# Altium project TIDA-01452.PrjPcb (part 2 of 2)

## Sheet TIDA-01452_Hart.SchDoc: Hart
size 431 x 279 mm; Date: Not shown in title block; ApprovedBy: Not shown in title block; CheckedBy: Not shown in title block; Author: Not shown in title block; CompanyName: Not shown in title block; DrawnBy: Il Han Kim; Engineer: Not shown in title block; Organization: Not shown in title block; Address1: Not shown in title block; Address2: Not shown in title block; Address3: Not shown in title block; Address4: Not shown in title block; DocumentNumber: 6; Revision: Use project parameter SCH_Rev; SheetNumber: 8; SheetTotal: 12; PageSetup: Record=PageOptions¦CenterHorizontal=True¦CenterVertical=True¦PrintScale=0.64¦XCorrection=1.00¦YCorrection=1.00¦PrintKind=0¦BorderSize=5000000¦LeftOffset=0¦BottomOffset=0¦Orientation=2¦PaperLength=1000¦PaperWidth=1000¦Scale=100¦PaperSource=15¦PrintQuality=600¦MediaType=1¦DitherType=10¦PrintScaleMode=1¦PaperKind=Letter
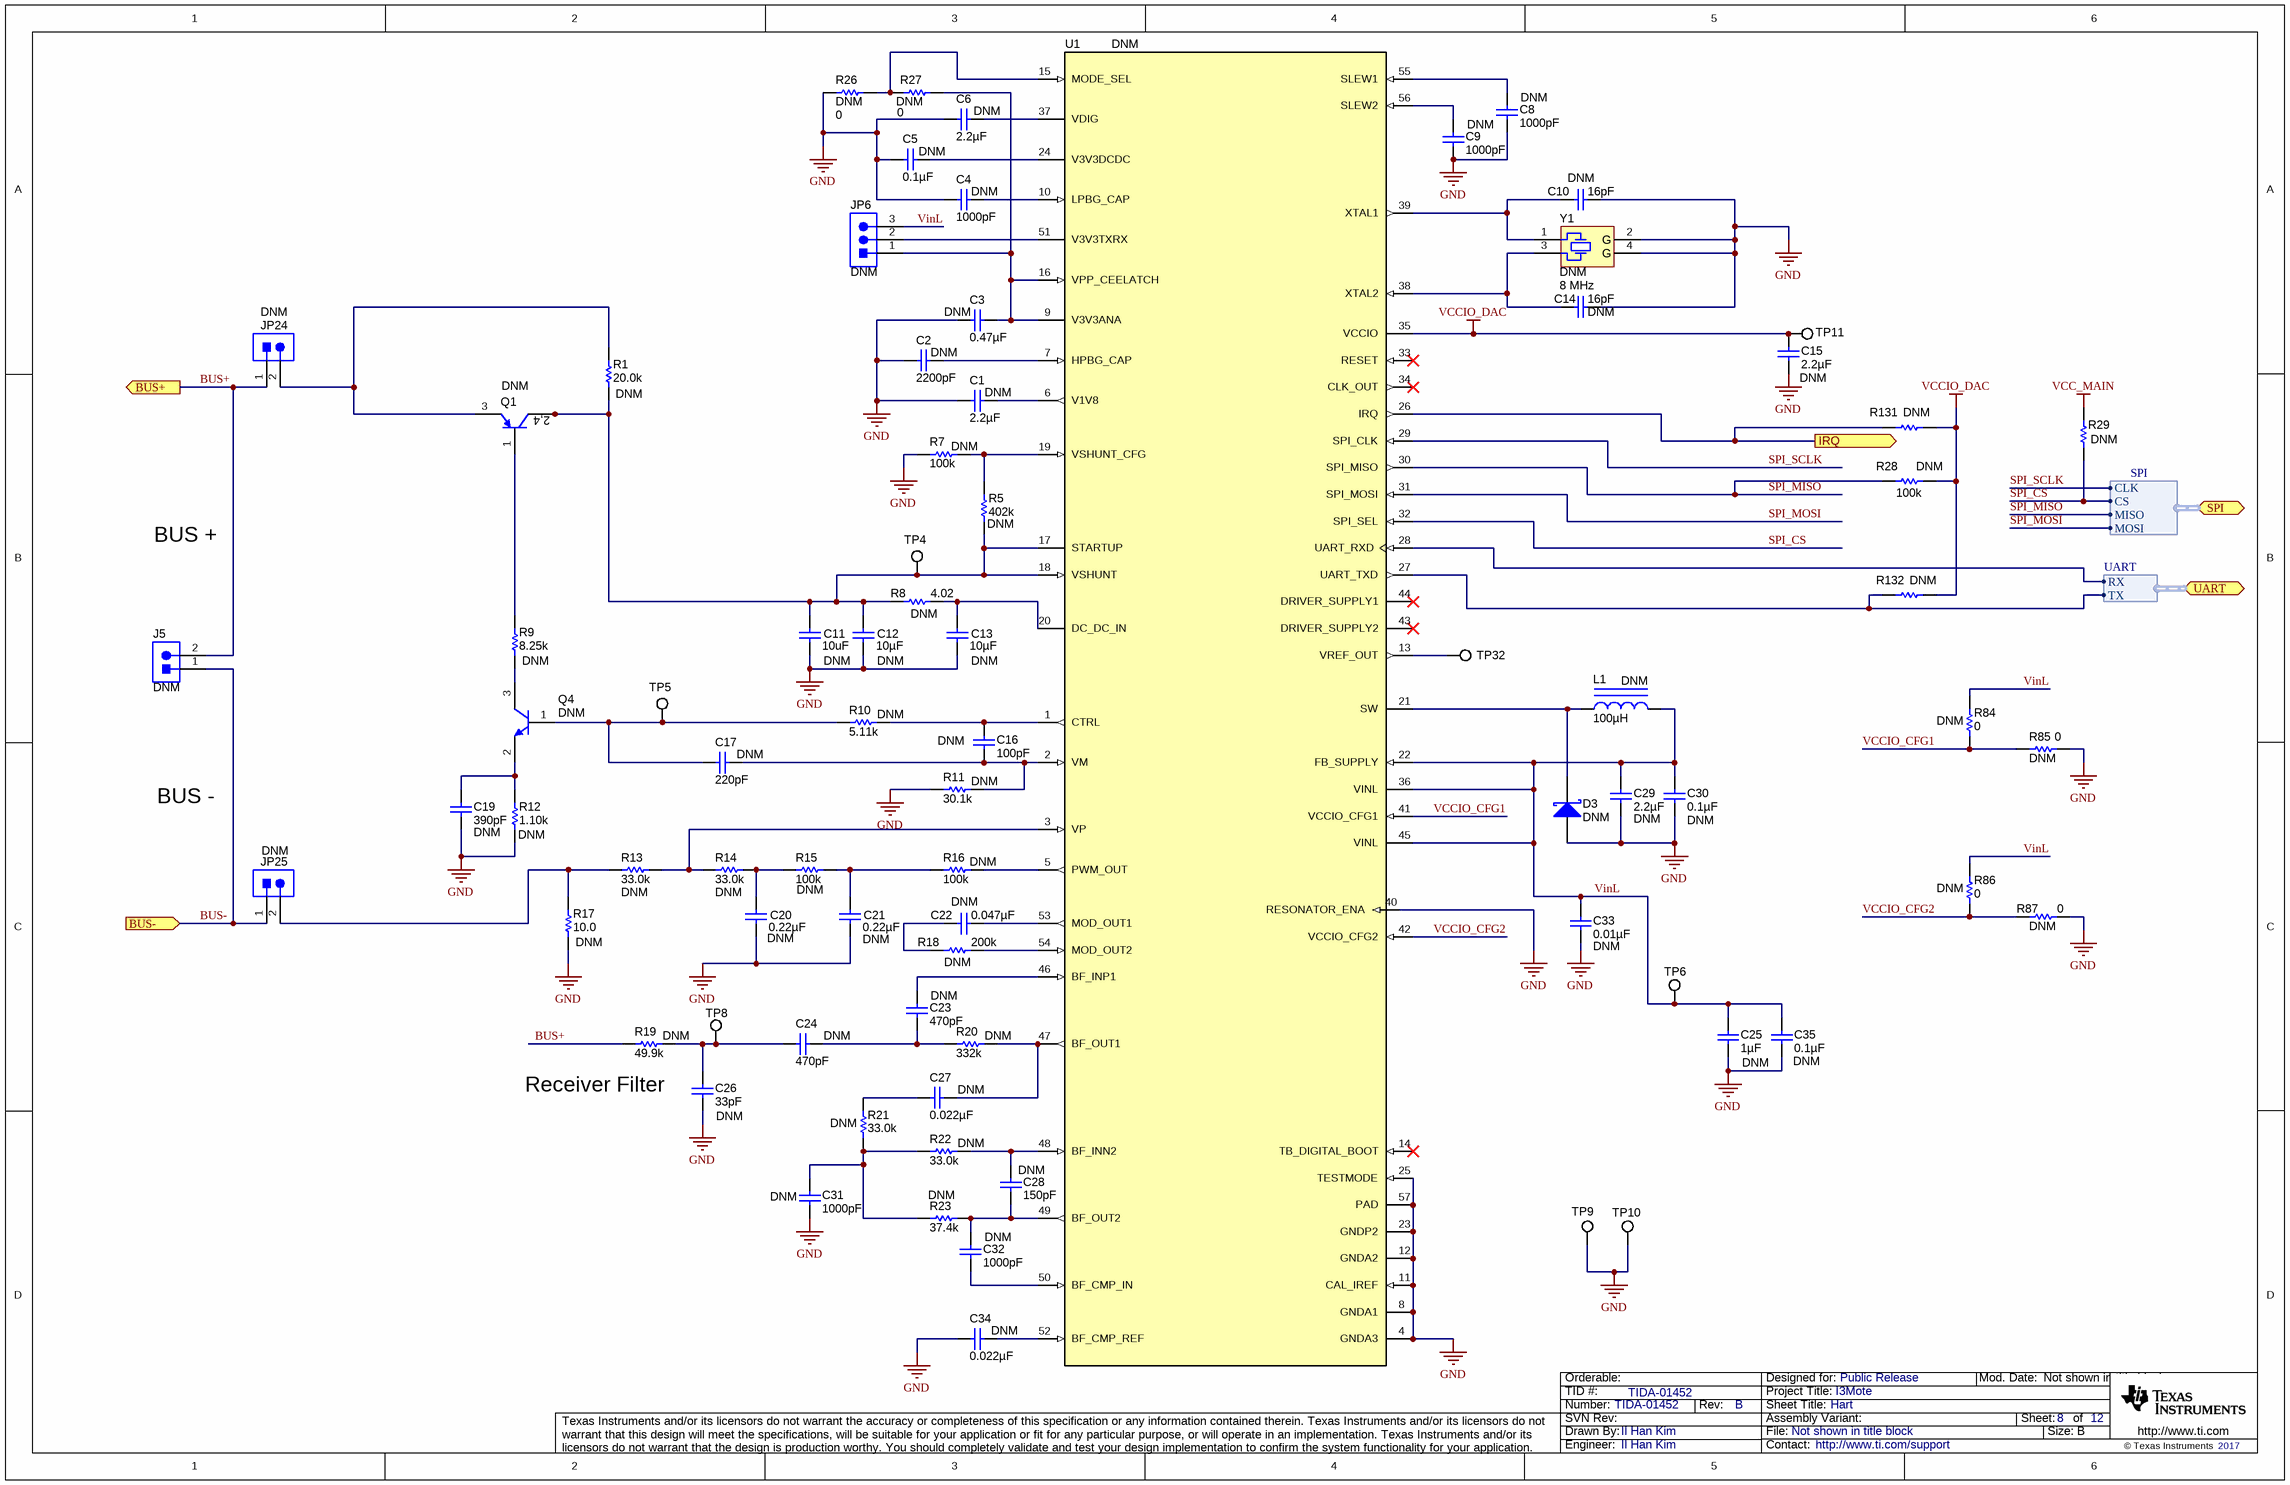
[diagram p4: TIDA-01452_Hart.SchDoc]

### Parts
C1  DNM  ValueDisplayed: 2.2µF  [0402]
C2  DNM  ValueDisplayed: 2200pF  [0402]
C3  DNM  ValueDisplayed: 0.47µF  [0402]
C4  DNM  ValueDisplayed: 1000pF  [0402]
C5  DNM  ValueDisplayed: 0.1µF  [0402]
C6  DNM  ValueDisplayed: 2.2µF  [0402]
C8  DNM  ValueDisplayed: 1000pF  [0402]
C9  DNM  ValueDisplayed: 1000pF  [0402]
C10  DNM  ValueDisplayed: 16pF  [0402]
C11  DNM  ValueDisplayed: 10uF  [1206_190]
C12  DNM  ValueDisplayed: 10µF  [1206_190]
C13  DNM  ValueDisplayed: 10µF  [1206_190]
C14  DNM  ValueDisplayed: 16pF  [0402]
C15  DNM  ValueDisplayed: 2.2µF  [0805_HV]
C16  DNM  ValueDisplayed: 100pF  [0402]
C17  DNM  ValueDisplayed: 220pF  [0402]
C19  DNM  ValueDisplayed: 390pF  [0402]
C20  DNM  ValueDisplayed: 0.22µF  [0603]
C21  DNM  ValueDisplayed: 0.22µF  [0603]
C22  DNM  ValueDisplayed: 0.047µF  [0402]
C23  DNM  ValueDisplayed: 470pF  [0402]
C24  DNM  ValueDisplayed: 470pF  [0402]
C25  DNM  ValueDisplayed: 1µF  [0402]
C26  DNM  ValueDisplayed: 33pF  [0402]
C27  DNM  ValueDisplayed: 0.022µF  [0402]
C28  DNM  ValueDisplayed: 150pF  [0402]
C29  DNM  ValueDisplayed: 2.2µF  [0805_HV]
C30  DNM  ValueDisplayed: 0.1µF  [0402]
C31  DNM  ValueDisplayed: 1000pF  [0402]
C32  DNM  ValueDisplayed: 1000pF  [0402]
C33  DNM  ValueDisplayed: 0.01µF  [0402]
C34  DNM  ValueDisplayed: 0.022µF  [0402]
C35  DNM  ValueDisplayed: 0.1µF  [0402]
D3  DNM  [sod-323]
J5  DNM  [TERM_BLK_ED555-2DS]
JP6  DNM  [CONN_TMM-103-01-T-S]
JP24  DNM  [CONN_TMM-102-01-T-S]
JP25  DNM  [CONN_TMM-102-01-T-S]
L1  DNM  ValueDisplayed: 100µH  [CBC3225]
Q1  DNM  [SOT-89-3]
Q4  DNM  [SOT-23]
R1  DNM  ValueDisplayed: 20.0k  [0603]
R5  DNM  ValueDisplayed: 402k  [0402]
R7  DNM  ValueDisplayed: 100k  [0402]
R8  DNM  ValueDisplayed: 4.02  [0603]
R9  DNM  ValueDisplayed: 8.25k  [0603]
R10  DNM  ValueDisplayed: 5.11k  [0402]
R11  DNM  ValueDisplayed: 30.1k  [0402]
R12  DNM  ValueDisplayed: 1.10k  [0603]
R13  DNM  ValueDisplayed: 33.0k  [0402]
R14  DNM  ValueDisplayed: 33.0k  [0402]
R15  DNM  ValueDisplayed: 100k  [0402]
R16  DNM  ValueDisplayed: 100k  [0402]
R17  DNM  ValueDisplayed: 10.0  [0603]
R18  DNM  ValueDisplayed: 200k  [0402]
R19  DNM  ValueDisplayed: 49.9k  [0402]
R20  DNM  ValueDisplayed: 332k  [0402]
R21  DNM  ValueDisplayed: 33.0k  [0402]
R22  DNM  ValueDisplayed: 33.0k  [0402]
R23  DNM  ValueDisplayed: 37.4k  [0402]
R26  DNM  ValueDisplayed: 0  [0402]
R27  DNM  ValueDisplayed: 0  [0402]
R28  DNM  ValueDisplayed: 100k  [0402]
R29  DNM  [0402]
R84  DNM  value 0  [0402]
R85  DNM  value 0  [0402]
R86  DNM  value 0  [0402]
R87  DNM  ValueDisplayed: 0  [0402]
R131  DNM  [0402]
R132  DNM  [0402]
TP4  NA  [TPS0.8]  (value not drawn)  (no BOM)
TP5  NA  [TPS0.8]  (value not drawn)  (no BOM)
TP6  NA  [TPS0.8]  (value not drawn)  (no BOM)
TP8  NA  [TPS0.8]  (value not drawn)  (no BOM)
TP9  NA  [TPS0.8]  (value not drawn)  (no BOM)
TP10  NA  [TPS0.8]  (value not drawn)  (no BOM)
TP11  NA  [TPS0.8]  (value not drawn)  (no BOM)
TP32  NA  [TPS0.8]  (value not drawn)  (no BOM)
U1  DNM  [DAC8730]
Y1  DNM  Frequency: 8 MHz  [XTL14S]

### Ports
BUS+ (out), BUS- (in), IRQ (out), SPI (harness SPI), UART (harness UART)

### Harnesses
SPI: CLK, CS, MISO, MOSI
UART: RX, TX

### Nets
GND: C1.2 C2.2 C3.2 C4.2 C5.2 C6.2 C8.2 C9.2 C10.1 C11.2 C12.2 C13.2 C14.1 C15.1 C19.2 C20.2 C21.2 C25.2 C26.2 C29.2 C30.2 C31.2 C33.2 C34.2 C35.2 D3.2(A) R7.2 R11.1 R12.2 R17.1 R26.2 R85.2 R87.1 TP9.1 TP10.1 U1.4(GNDA3) U1.8(GNDA1) U1.11(CAL_IREF) U1.12(GNDA2) U1.23(GNDP2) U1.25(TESTMODE) U1.40(RESONATOR_ENA) U1.57(PAD) Y1.2(GND) Y1.4(GND)
VCC_MAIN: R29.1
VCCIO_DAC: C15.2 R28.1 R131.1 R132.1 TP11.1 U1.35(VCCIO)
BUS+: J5.2 JP24.1 R19.1 ; port BUS+
BUS-: J5.1 JP25.1 ; port BUS-
CC2650_DAC8730_IRQ: R131.2 U1.26(IRQ) ; port IRQ
CC2650_DAC8730_UART_RX: R132.2 U1.27(UART_TXD) ; port UART.TX
CC2650_DAC8730_UART_TX: U1.28(UART_RXD) ; port UART.RX
SPI_CS: R29.2 U1.32(SPI_SEL) ; port SPI.CS  [project net CC2650_DAC8730_SPI_CS]
SPI_MISO: R28.2 U1.30(SPI_MISO) ; port SPI.MISO  [project net CC2650_DAC8730_SPI_MISO]
SPI_MOSI: U1.31(SPI_MOSI) ; port SPI.MOSI  [project net CC2650_DAC8730_SPI_MOSI]
SPI_SCLK: U1.29(SPI_CLK) ; port SPI.CLK  [project net CC2650_DAC8730_SPI_CLK]
VCCIO_CFG1: R84.1 R85.1 U1.41(VCCIO_CFG1)
VCCIO_CFG2: R86.1 R87.2 U1.42(VCCIO_CFG2)
VinL: C25.1 C29.1 C30.1 C33.1 C35.1 JP6.3 L1.2 R84.2 R86.2 TP6.1 U1.22(FB_SUPPLY) U1.36(VINL) U1.45(VINL)
NetC1_1: C1.1 U1.6(V1V8)
NetC2_1: C2.1 U1.7(HPBG_CAP)
NetC3_1: C3.1 JP6.1 R27.1 U1.9(V3V3ANA) U1.16(VPP_CEELATCH)
NetC4_1: C4.1 U1.10(LPBG_CAP)
NetC5_1: C5.1 U1.24(V3V3DCDC)
NetC6_1: C6.1 U1.37(VDIG)
NetC8_1: C8.1 U1.55(SLEW1)
NetC9_1: C9.1 U1.56(SLEW2)
NetC10_2: C10.2 U1.39(XTAL1) Y1.1
NetC11_1: C11.1 C12.1 Q1.2(C) Q1.4(C) R1.1 R5.1 R8.1 TP4.1 U1.17(STARTUP) U1.18(VSHUNT)
NetC13_1: C13.1 R8.2 U1.20(DC_DC_IN)
NetC14_2: C14.2 U1.38(XTAL2) Y1.3
NetC16_1: C16.1 R10.2 U1.1(CTRL)
NetC16_2: C16.2 C17.1 R11.2 U1.2(VM)
NetC17_2: C17.2 Q4.1(B) R10.1 TP5.1
NetC19_1: C19.1 Q4.2(E) R12.1
NetC20_1: C20.1 R14.2 R15.1
NetC21_1: C21.1 R15.2 R16.1
NetC22_1: C22.1 U1.53(MOD_OUT1)
NetC22_2: C22.2 R18.1
NetC23_1: C23.1 U1.46(BF_INP1)
NetC23_2: C23.2 C24.1 R20.1
NetC24_2: C24.2 C26.1 R19.2 TP8.1
NetC27_1: C27.1 R20.2 U1.47(BF_OUT1)
NetC27_2: C27.2 R21.2
NetC28_1: C28.1 R22.2 U1.48(BF_INN2)
NetC28_2: C28.2 C32.1 R23.2 U1.49(BF_OUT2)
NetC31_1: C31.1 R21.1 R22.1 R23.1
NetC32_2: C32.2 U1.50(BF_CMP_IN)
NetC34_1: C34.1 U1.52(BF_CMP_REF)
NetD3_1: D3.1(K) L1.1 U1.21(SW)
NetJP6_2: JP6.2 U1.51(V3V3TXRX)
NetJP24_2: JP24.2 Q1.3(E) R1.2
NetJP25_2: JP25.2 R13.1 R17.2
NetQ1_1: Q1.1(B) R9.2
NetQ4_3: Q4.3(C) R9.1
NetR5_2: R5.2 R7.1 U1.19(VSHUNT_CFG)
NetR13_2: R13.2 R14.1 U1.3(VP)
NetR16_2: R16.2 U1.5(PWM_OUT)
NetR18_2: R18.2 U1.54(MOD_OUT2)
NetR26_1: R26.1 R27.2 U1.15(MODE_SEL)
NetTP32_1: TP32.1 U1.13(VREF_OUT)

Not connected (* = marked no-connect by the designer): U1 14(TB_DIGITAL_BOOT)* 33(RESET)* 34(CLK_OUT)* 43(DRIVER_SUPPLY2)* 44(DRIVER_SUPPLY1)*

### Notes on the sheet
- BUS +
- BUS -
- Receiver Filter

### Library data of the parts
C1 C6 = C1005X5R1E225K050BC: CAP, CERM, 2.2 µF, 25 V, +/- 10%, X5R, 0402; Manufacturer: TDK; Polarized: N; CompType: Capacitor; Value: 2.2uF; U/M: EA; Cap_F: 0.0000022; Tolerance_%: 10; Value1: Unknown; VDC_V: 25; Value2: 25V; TaMin_C: -55; TaMax_C: 85; AEC Category: Q200
C2 = GRM155R71H222KA01D: CAP, CERM, 2200 pF, 50 V, +/- 10%, X7R, 0402; Manufacturer: MuRata; Polarized: N; CompType: Capacitor; Value: 2200pF; U/M: EA; Cap_F: 0.0000000022; Tolerance_%: 10; Value1: Unknown; VDC_V: 50; Value2: 50V; TaMin_C: -55; TaMax_C: 125; AEC Category: Q200
C3 = GRM155R61C474KE01: CAP, CERM, 0.47 µF, 16 V, +/- 10%, X5R, 0402; Manufacturer: MuRata; Polarized: N; CompType: Capacitor; Value: 0.47uF; U/M: EA; Cap_F: 0.00000047; Tolerance_%: 10; Value1: Unknown; VDC_V: 16; Value2: 16V; TaMin_C: -55; TaMax_C: 85; AEC Category: Q200
C4 C8 C9 C31 C32 = GRM1555C1H102JA01D: CAP, CERM, 1000 pF, 50 V, +/- 5%, C0G/NP0, 0402; Manufacturer: MuRata; Polarized: N; CompType: Capacitor; Value: 1000pF; U/M: EA; Cap_F: 0.000000001; Tolerance_%: 5; Value1: Unknown; VDC_V: 50; Value2: 50V; TaMin_C: -55; TaMax_C: 125; AEC Category: Q200
C5 C30 C35 = GCM155R71H104KE02D: CAP, CERM, 0.1 µF, 50 V, +/- 10%, X7R, AEC-Q200 Grade 1, 0402; Manufacturer: MuRata; Polarized: N; CompType: Capacitor; Value: 0.1uF; U/M: EA; Cap_F: 0.0000001; Tolerance_%: 10; Value1: Unknown; VDC_V: 50; Value2: 50V; TaMin_C: -55; TaMax_C: 125; AEC Category: Q200; AEC Qualified: Y; AEC Grade: 1
C10 C14 = GRM1555C1H160JA01D: CAP, CERM, 16 pF, 50 V, +/- 5%, C0G/NP0, 0402; Manufacturer: MuRata; Polarized: N; CompType: Capacitor; Value: 16pF; U/M: EA; Cap_F: 0.000000000016; Tolerance_%: 5; Value1: Unknown; VDC_V: 50; Value2: 50V; TaMin_C: -55; TaMax_C: 125; SizeArea_mm2: 0.5; SizeAreaWB_mm2: 3; SizeX_mm: 1; SizeZ_mm: 0.6; AEC Category: Q200
C11 = C1206C106K3RACTU: Cap Cerm. MLCC 10uF 25 Volts 10% X7R 1206; Manufacturer: Kemet; Polarized: N; CompType: Capacitor; U/M: EA; Cap_F: 0.00001; Tolerance_%: 10; Value1: Unknown; VDC_V: 25; Value2: 25V; TaMin_C: -55; TaMax_C: 125; Cap_Case: 1206; AEC Category: Q200
C12 C13 = C1206C106K3RACTU: CAP, CERM, 10 µF, 25 V, +/- 10%, X7R, 1206_190; Manufacturer: Kemet; Polarized: N; CompType: Capacitor; Value: 10uF; U/M: EA; Cap_F: 0.00001; Tolerance_%: 10; Value1: Unknown; VDC_V: 25; Value2: 25V; TaMin_C: -55; TaMax_C: 125; Cap_Case: 1206; AEC Category: Q200
C15 C29 = C0805C225K4RACTU: CAP, CERM, 2.2 µF, 16 V, +/- 10%, X7R, 0805; Manufacturer: Kemet; Polarized: N; CompType: Capacitor; Value: 2.2uF; U/M: EA; Cap_F: 0.0000022; Tolerance_%: 10; ESR_ohm: 0.008; Value1: 0.008 ohm; VDC_V: 16; Value2: 16V; IRMS_A: 15.55; TaMin_C: -55; TaMax_C: 125; Cap_Case: 0805; AEC Category: Q200
C16 = GRM1535C1H101JDD5D: CAP, CERM, 100 pF, 50 V, +/- 5%, C0G/NP0, 0402; Manufacturer: MuRata; Polarized: N; CompType: Capacitor; Value: 100pF; U/M: EA; Cap_F: 0.0000000001; Tolerance_%: 5; Value1: Unknown; VDC_V: 50; Value2: 50V; TaMin_C: -55; TaMax_C: 125; AEC Category: Q200
C17 = GRM1555C1H221JA01D: CAP, CERM, 220 pF, 50 V, +/- 5%, C0G/NP0, 0402; Manufacturer: MuRata; Polarized: N; CompType: Capacitor; Value: 220pF; U/M: EA; Cap_F: 0.00000000022; Tolerance_%: 5; Value1: Unknown; VDC_V: 50; Value2: 50V; TaMin_C: -55; TaMax_C: 125; AEC Category: Q200
C19 = GRM1555C1H391JA01D: CAP, CERM, 390 pF, 50 V, +/- 5%, C0G/NP0, 0402; Manufacturer: MuRata; Polarized: N; CompType: Capacitor; Value: 390pF; U/M: EA; Cap_F: 0.00000000039; Tolerance_%: 5; Value1: Unknown; VDC_V: 50; Value2: 50V; TaMin_C: -55; TaMax_C: 125; AEC Category: Q200
C20 C21 = 885012206048: CAP, CERM, 0.22 µF, 16 V, +/- 10%, X7R, 0603; Manufacturer: Wurth Elektronik; Polarized: N; CompType: Capacitor; Value: 0.22uF; U/M: EA; Cap_F: 0.00000022; Tolerance_%: 10; Value1: Unknown; VDC_V: 16; Value2: 16V; TaMin_C: -55; TaMax_C: 125; AEC Category: Q200
C22 = C1005X7R1H473K050BB: CAP, CERM, 0.047 µF, 50 V, +/- 10%, X7R, 0402; Manufacturer: TDK; Polarized: N; CompType: Capacitor; Value: 0.047uF; U/M: EA; Cap_F: 0.000000047; Tolerance_%: 10; Value1: Unknown; VDC_V: 50; Value2: 50V; TaMin_C: -55; TaMax_C: 125; AEC Category: Q200
C23 C24 = GRM1555C1H471JA01D: CAP, CERM, 470 pF, 50 V, +/- 5%, C0G/NP0, 0402; Manufacturer: MuRata; Polarized: N; CompType: Capacitor; Value: 470pF; U/M: EA; Cap_F: 0.00000000047; Tolerance_%: 5; Value1: Unknown; VDC_V: 50; Value2: 50V; TaMin_C: -55; TaMax_C: 125; AEC Category: Q200
C25 = GRM155R61E105KA12D: CAP, CERM, 1 µF, 25 V, +/- 10%, X5R, 0402; Manufacturer: MuRata; Polarized: N; CompType: Capacitor; Value: 1uF; U/M: EA; Cap_F: 0.000001; Tolerance_%: 10; Value1: Unknown; VDC_V: 25; Value2: 25V; TaMin_C: -55; TaMax_C: 85; AEC Category: Q200
C26 = GRM1555C1H330JA01D: CAP, CERM, 33 pF, 50 V, +/- 5%, C0G/NP0, 0402; Manufacturer: MuRata; Polarized: N; CompType: Capacitor; Value: 33pF; U/M: EA; Cap_F: 0.000000000033; Tolerance_%: 5; Value1: Unknown; VDC_V: 50; Value2: 50V; TaMin_C: -55; TaMax_C: 125; AEC Category: Q200
C27 C34 = GCM155R71H223KA55D: CAP, CERM, 0.022 µF, 50 V, +/- 10%, C0G/NP0, 0402; Manufacturer: MuRata; Polarized: N; CompType: Capacitor; Value: 0.022uF; U/M: EA; Cap_F: 0.000000022; Tolerance_%: 10; Value1: Unknown; VDC_V: 50; Value2: 50V; TaMin_C: -55; TaMax_C: 125; AEC Category: Q200
C28 = GRM1555C1H151JA01D: CAP, CERM, 150 pF, 50 V, +/- 5%, C0G/NP0, 0402; Manufacturer: MuRata; Polarized: N; CompType: Capacitor; Value: 150pF; U/M: EA; Cap_F: 0.00000000015; Tolerance_%: 5; Value1: Unknown; VDC_V: 50; Value2: 50V; TaMin_C: -55; TaMax_C: 125; AEC Category: Q200
C33 = GCM155R71H103KA55D: CAP, CERM, 0.01 µF, 50 V, +/- 10%, C0G/NP0, 0402; Manufacturer: MuRata; Polarized: N; CompType: Capacitor; Value: 0.01uF; U/M: EA; Cap_F: 0.00000001; Tolerance_%: 10; Value1: Unknown; VDC_V: 50; Value2: 50V; TaMin_C: -55; TaMax_C: 125; AEC Category: Q200
D3 = BAT54WS-7-F: Diode, Schottky, 30 V, 0.2 A, SOD-323; Manufacturer: Diodes Inc.; U/M: EA; Vf_V: 0.7; Value: 30V; Value1: 0.2A; Value2: 0.7V; Io_A: 0.2; Vr_V: 30; TJmax_C: 125; AEC Category: Q101
J5 = ED555/2DS: Terminal Block, 6A, 3.5mm Pitch, 2-Pos, TH; Manufacturer: On-Shore Technology; SymbolCreator: a0412235; CompType: Connector; U/M: EA
JP6 = TMM-103-01-T-S: Header, 2mm, 3x1, Tin, TH; Manufacturer: Samtec; SymbolCreator: a0799628; U/M: EA
JP24 JP25 = TMM-102-01-T-S: Header, 2mm, 2x1, Tin, TH; Manufacturer: Samtec; SymbolCreator: a0412235; U/M: EA
L1 = CBC3225T101MR: Inductor, Wirewound, 100 µH, 0.27 A, 1.4 ohm, SMD; Manufacturer: Taiyo Yuden; Value: 100uH; Ind_H: 100.0E-6; Imax_A: 0.27; Irms: 0.34A @ 40C rise; Isat: 0.27A @ 30% inductance drop; DCR_ohm: 1.4; Value1: 1.4 ohm; Value2: 0.27A; AEC Category: Q200; AEC Qualified: N
Q1 = 2SB1260T100R, Rohm: Transistor, PNP, 80 V, 1 A, SOT-89; Manufacturer: Rohm; CompType: BJT; PNP: 1; NPN: 0; Vceo_V: 80; Vcesat1_V: 0.4; Value: 80 V; Value1: 1 A; HfeMax: 390; TaMin_C: -55; TaMax_C: 150; U/M: EA; AEC Category: Q101
Q4 = BC846BLT1G, ON Semiconductor: Transistor, NPN, 65 V, 0.1 A, SOT-23; CompType: BJT; PNP: 0; NPN: 1; Vceo_V: 65; Vcesat1_V: 0.7; Value: 65 V; IcRated_A: 0.1; Value1: 0.1 A; HfeMax: 450; TaMin_C: -55; TaMax_C: 150; U/M: EA; AEC Category: Q101
R1 = RC0603FR-0720KL: RES, 20.0 k, 1%, 0.1 W, 0603; Manufacturer: Yageo America; CompType: Resistor; Value: 20.0k; Res_ohm: 20000; Value_Code: 20k0; Tolerance_%: 1; Power_W: 0.1; Value2: 0.1W; VDC_V: 150; TempCo: 200 ppm/C; EIA_Code: E96; U/M: EA; AEC Category: Q200
R5 = CRCW0402402KFKED: RES, 402 k, 1%, 0.063 W, 0402; Manufacturer: Vishay-Dale; CompType: Resistor; Value: 402k; Res_ohm: 402000; Tolerance_%: 1; Power_W: 0.063; Value2: 0.063W; VDC_V: 50; TempCo: 100 ppm/C; EIA_Code: E96; U/M: EA; AEC Category: Q200
R7 R15 R16 R28 R29 R131 R132 = CRCW0402100KFKED: RES, 100 k, 1%, 0.063 W, 0402; Manufacturer: Vishay-Dale; CompType: Resistor; Value: 100k; Res_ohm: 100000; Tolerance_%: 1; Power_W: 0.063; Value2: 0.063W; VDC_V: 50; TempCo: 100 ppm/C; EIA_Code: E96; U/M: EA; AEC Category: Q200
R8 = CRCW06034R02FKEA: RES, 4.02, 1%, 0.1 W, 0603; Manufacturer: Vishay-Dale; CompType: Resistor; Value: 4.02; Value_Code: 4R02; Tolerance_%: 1; Power_W: 0.1; Value2: 0.1W; VDC_V: 75; TempCo: 100 ppm/C; EIA_Code: E96; U/M: EA; AEC Category: Q200
R9 = CRCW06038K25FKEA: RES, 8.25 k, 1%, 0.1 W, 0603; Manufacturer: Vishay-Dale; CompType: Resistor; Value: 8.25k; Res_ohm: 8250; Value_Code: 8k25; Tolerance_%: 1; Power_W: 0.1; Value2: 0.1W; VDC_V: 75; TempCo: 100 ppm/C; EIA_Code: E96; U/M: EA; AEC Category: Q200
R10 = CRCW04025K11FKED: RES, 5.11 k, 1%, 0.063 W, 0402; Manufacturer: Vishay-Dale; CompType: Resistor; Value: 5.11k; Res_ohm: 5110; Value_Code: 5k11; Tolerance_%: 1; Power_W: 0.063; Value2: 0.063W; VDC_V: 50; TempCo: 100 ppm/C; EIA_Code: E96; U/M: EA; AEC Category: Q200
R11 = CRCW040230K1FKED: RES, 30.1 k, 1%, 0.063 W, 0402; Manufacturer: Vishay-Dale; CompType: Resistor; Value: 30.1k; Res_ohm: 30100; Value_Code: 30k1; Tolerance_%: 1; Power_W: 0.063; Value2: 0.063W; VDC_V: 50; TempCo: 100 ppm/C; EIA_Code: E96; U/M: EA; AEC Category: Q200
R12 = CRCW06031K10FKEA: RES, 1.10 k, 1%, 0.1 W, 0603; Manufacturer: Vishay-Dale; CompType: Resistor; Value: 1.10k; Res_ohm: 1100; Value_Code: 1k10; Tolerance_%: 1; Power_W: 0.1; Value2: 0.1W; VDC_V: 75; TempCo: 100 ppm/C; EIA_Code: E96; U/M: EA; AEC Category: Q200
R13 R14 R21 R22 = ERA-2AEB333X: RES, 33.0 k, 0.1%, 0.063 W, 0402; Manufacturer: Panasonic; CompType: Resistor; Value: 33.0k; Res_ohm: 33000; Value_Code: 33k0; Tolerance_%: 0.1; Power_W: 0.063; Value2: 0.063W; VDC_V: 50; TempCo: 25 ppm/C; U/M: EA; AEC Category: Q200
R17 = CRCW060310R0FKEA: RES, 10.0, 1%, 0.1 W, 0603; Manufacturer: Vishay-Dale; CompType: Resistor; Value: 10.0; Res_ohm: 10; Value_Code: 10R0; Tolerance_%: 1; Power_W: 0.1; Value2: 0.1W; VDC_V: 75; TempCo: 100 ppm/C; EIA_Code: E96; U/M: EA; AEC Category: Q200
R18 = CRCW0402200KFKED: RES, 200 k, 1%, 0.063 W, 0402; Manufacturer: Vishay-Dale; CompType: Resistor; Value: 200k; Res_ohm: 200000; Tolerance_%: 1; Power_W: 0.063; Value2: 0.063W; VDC_V: 50; TempCo: 100 ppm/C; EIA_Code: E96; U/M: EA; AEC Category: Q200
R19 = CRCW040249K9FKED: RES, 49.9 k, 1%, 0.063 W, 0402; Manufacturer: Vishay-Dale; CompType: Resistor; Value: 49.9k; Res_ohm: 49900; Value_Code: 49k9; Tolerance_%: 1; Power_W: 0.063; Value2: 0.063W; VDC_V: 50; TempCo: 100 ppm/C; EIA_Code: E96; U/M: EA; AEC Category: Q200
R20 = CRCW0402332KFKED: RES, 332 k, 1%, 0.063 W, 0402; Manufacturer: Vishay-Dale; CompType: Resistor; Value: 332k; Res_ohm: 332000; Tolerance_%: 1; Power_W: 0.063; Value2: 0.063W; VDC_V: 50; TempCo: 100 ppm/C; EIA_Code: E96; U/M: EA; AEC Category: Q200
R23 = CRCW040237K4FKED: RES, 37.4 k, 1%, 0.063 W, 0402; Manufacturer: Vishay-Dale; CompType: Resistor; Value: 37.4k; Res_ohm: 37400; Value_Code: 37k4; Tolerance_%: 1; Power_W: 0.063; Value2: 0.063W; VDC_V: 50; TempCo: 100 ppm/C; EIA_Code: E96; U/M: EA; AEC Category: Q200
R26 = CRCW04020000Z0ED: RES, 0, 5%, 0.063 W, 0402; Manufacturer: Vishay-Dale; CompType: Resistor; Value: 0; Value_Code: 0000; Tolerance_%: 5; Power_W: 0.063; Value2: 0.063W; VDC_V: 50; TempCo: 200 ppm/C; EIA_Code: E24; U/M: EA; AEC Category: Q200
R27 R87 = CRCW04020000Z0ED: RES, 0, 5%, 0.063 W, 0402; Manufacturer: Vishay-Dale; CompType: Resistor; Value: 0; Value_Code: 0000; Tolerance_%: 5; Power_W: 0.063; Value2: 0.063W; VDC_V: 50; TempCo: 200 ppm/C; EIA_Code: E24; U/M: EA
R84-R86 = CRCW04020000Z0ED: RES, 0, 5%, 0.063 W, 0402; Manufacturer: Vishay-Dale; CompType: Resistor; Value_Code: 0000; Tolerance_%: 5; Power_W: 0.063; Value2: 0.063W; VDC_V: 50; TempCo: 200 ppm/C; EIA_Code: E24; U/M: EA
TP4-TP6 TP8-TP11 TP32 = TEST_POINT_ROUND_1.2: Round Test Point, 1.2mm diam.
U1 = DAC8730: DAC8730, DAC8730; Manufacturer: Texas Instruments; SymbolCreator: Altium; CompType: IC; U/M: EA
Y1 = ABM3B-8.000MHZ-10-1-U-T: Crystal, 8 MHz, 10 pF, SMD; Manufacturer: Abracon

## Sheet TIDA-01452_DEBUG_USB.SchDoc: DEBUG_USB
size 431 x 279 mm; Date: Not shown in title block; ApprovedBy: Not shown in title block; CheckedBy: Not shown in title block; Author: Not shown in title block; CompanyName: Not shown in title block; DrawnBy: Il Han Kim; Engineer: Not shown in title block; Organization: Not shown in title block; Address1: Not shown in title block; Address2: Not shown in title block; Address3: Not shown in title block; Address4: Not shown in title block; DocumentNumber: 5; Revision: Use project parameter SCH_Rev; SheetNumber: 11; SheetTotal: 12; PageSetup: Record=PageOptions¦CenterHorizontal=True¦CenterVertical=True¦PrintScale=1.00¦XCorrection=1.00¦YCorrection=1.00¦PrintKind=0¦BorderSize=5000000¦LeftOffset=0¦BottomOffset=0¦Orientation=2¦PaperLength=1000¦PaperWidth=1000¦Scale=100¦PaperSource=15¦PrintQuality=600¦MediaType=1¦DitherType=10¦PaperKind=Letter¦PrintScaleMode=1
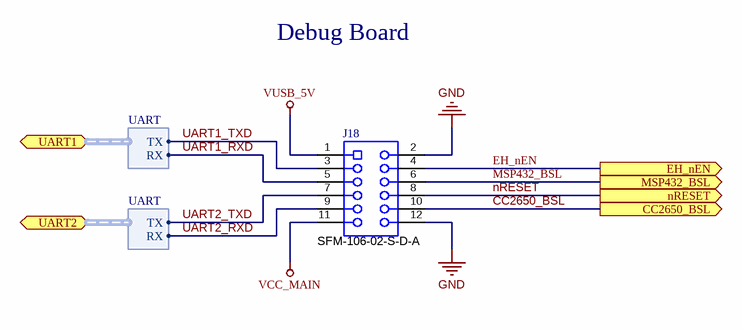
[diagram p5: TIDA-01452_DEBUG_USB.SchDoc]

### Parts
J18  SFM-106-02-S-D-A  [Samtec_SFM-106-02-x-D-A]

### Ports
CC2650_BSL (out), EH_nEN (out), MSP432_BSL (out), nRESET (out), UART1 (harness UART), UART2 (harness UART)

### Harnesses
UART: RX, TX

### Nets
GND: J18.2 J18.12
VCC_MAIN: J18.11
VUSB_5V: J18.1  [project net ISense-]
CC2650_BSL: J18.10 ; port CC2650_BSL
EH_nEN: J18.4 ; port EH_nEN
MSP432_BSL: J18.6 ; port MSP432_BSL
nRESET: J18.8 ; port nRESET  [project net CC2650_nRESET]
UART1_RXD: J18.5 ; port UART1.RX  [project net FTDI_UART1.RX]
UART1_TXD: J18.3 ; port UART1.TX  [project net FTDI_UART1.TX]
UART2_RXD: J18.9 ; port UART2.RX  [project net CC2650_FTDI_UART_TX]
UART2_TXD: J18.7 ; port UART2.TX  [project net CC2650_FTDI_UART_RX]

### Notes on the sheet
- Debug Board

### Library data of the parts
J18 = SFM-106-02-S-D-A: Receptacle, 1.27mm, 6x2, Gold, SMT; Manufacturer: Samtec; SymbolCreator: a0412235; Pitch_mm: 1.27; Gender: Female; Row_Count: 2; Current_A: 3.2; Voltage_V: 250; Cert_CSA: Y

## Sheet TIDA-01452_WirelessConnectivity.SchDoc: Connectivity
size 431 x 279 mm; Date: Not shown in title block; ApprovedBy: Not shown in title block; CheckedBy: Not shown in title block; Author: Not shown in title block; CompanyName: Not shown in title block; DrawnBy: Il Han Kim; Engineer: Not shown in title block; Organization: Not shown in title block; Address1: Not shown in title block; Address2: Not shown in title block; Address3: Not shown in title block; Address4: Not shown in title block; DocumentNumber: 12; Revision: Use project parameter SCH_Rev; SheetNumber: 7; SheetTotal: 12; PageSetup: Record=PageOptions¦CenterHorizontal=True¦CenterVertical=True¦PrintScale=1.00¦XCorrection=1.00¦YCorrection=1.00¦PrintKind=0¦BorderSize=5000000¦LeftOffset=0¦BottomOffset=0¦Orientation=2¦PaperLength=1000¦PaperWidth=1000¦Scale=100¦PaperSource=15¦PrintQuality=600¦MediaType=1¦DitherType=10¦PaperKind=Letter¦PrintScaleMode=1
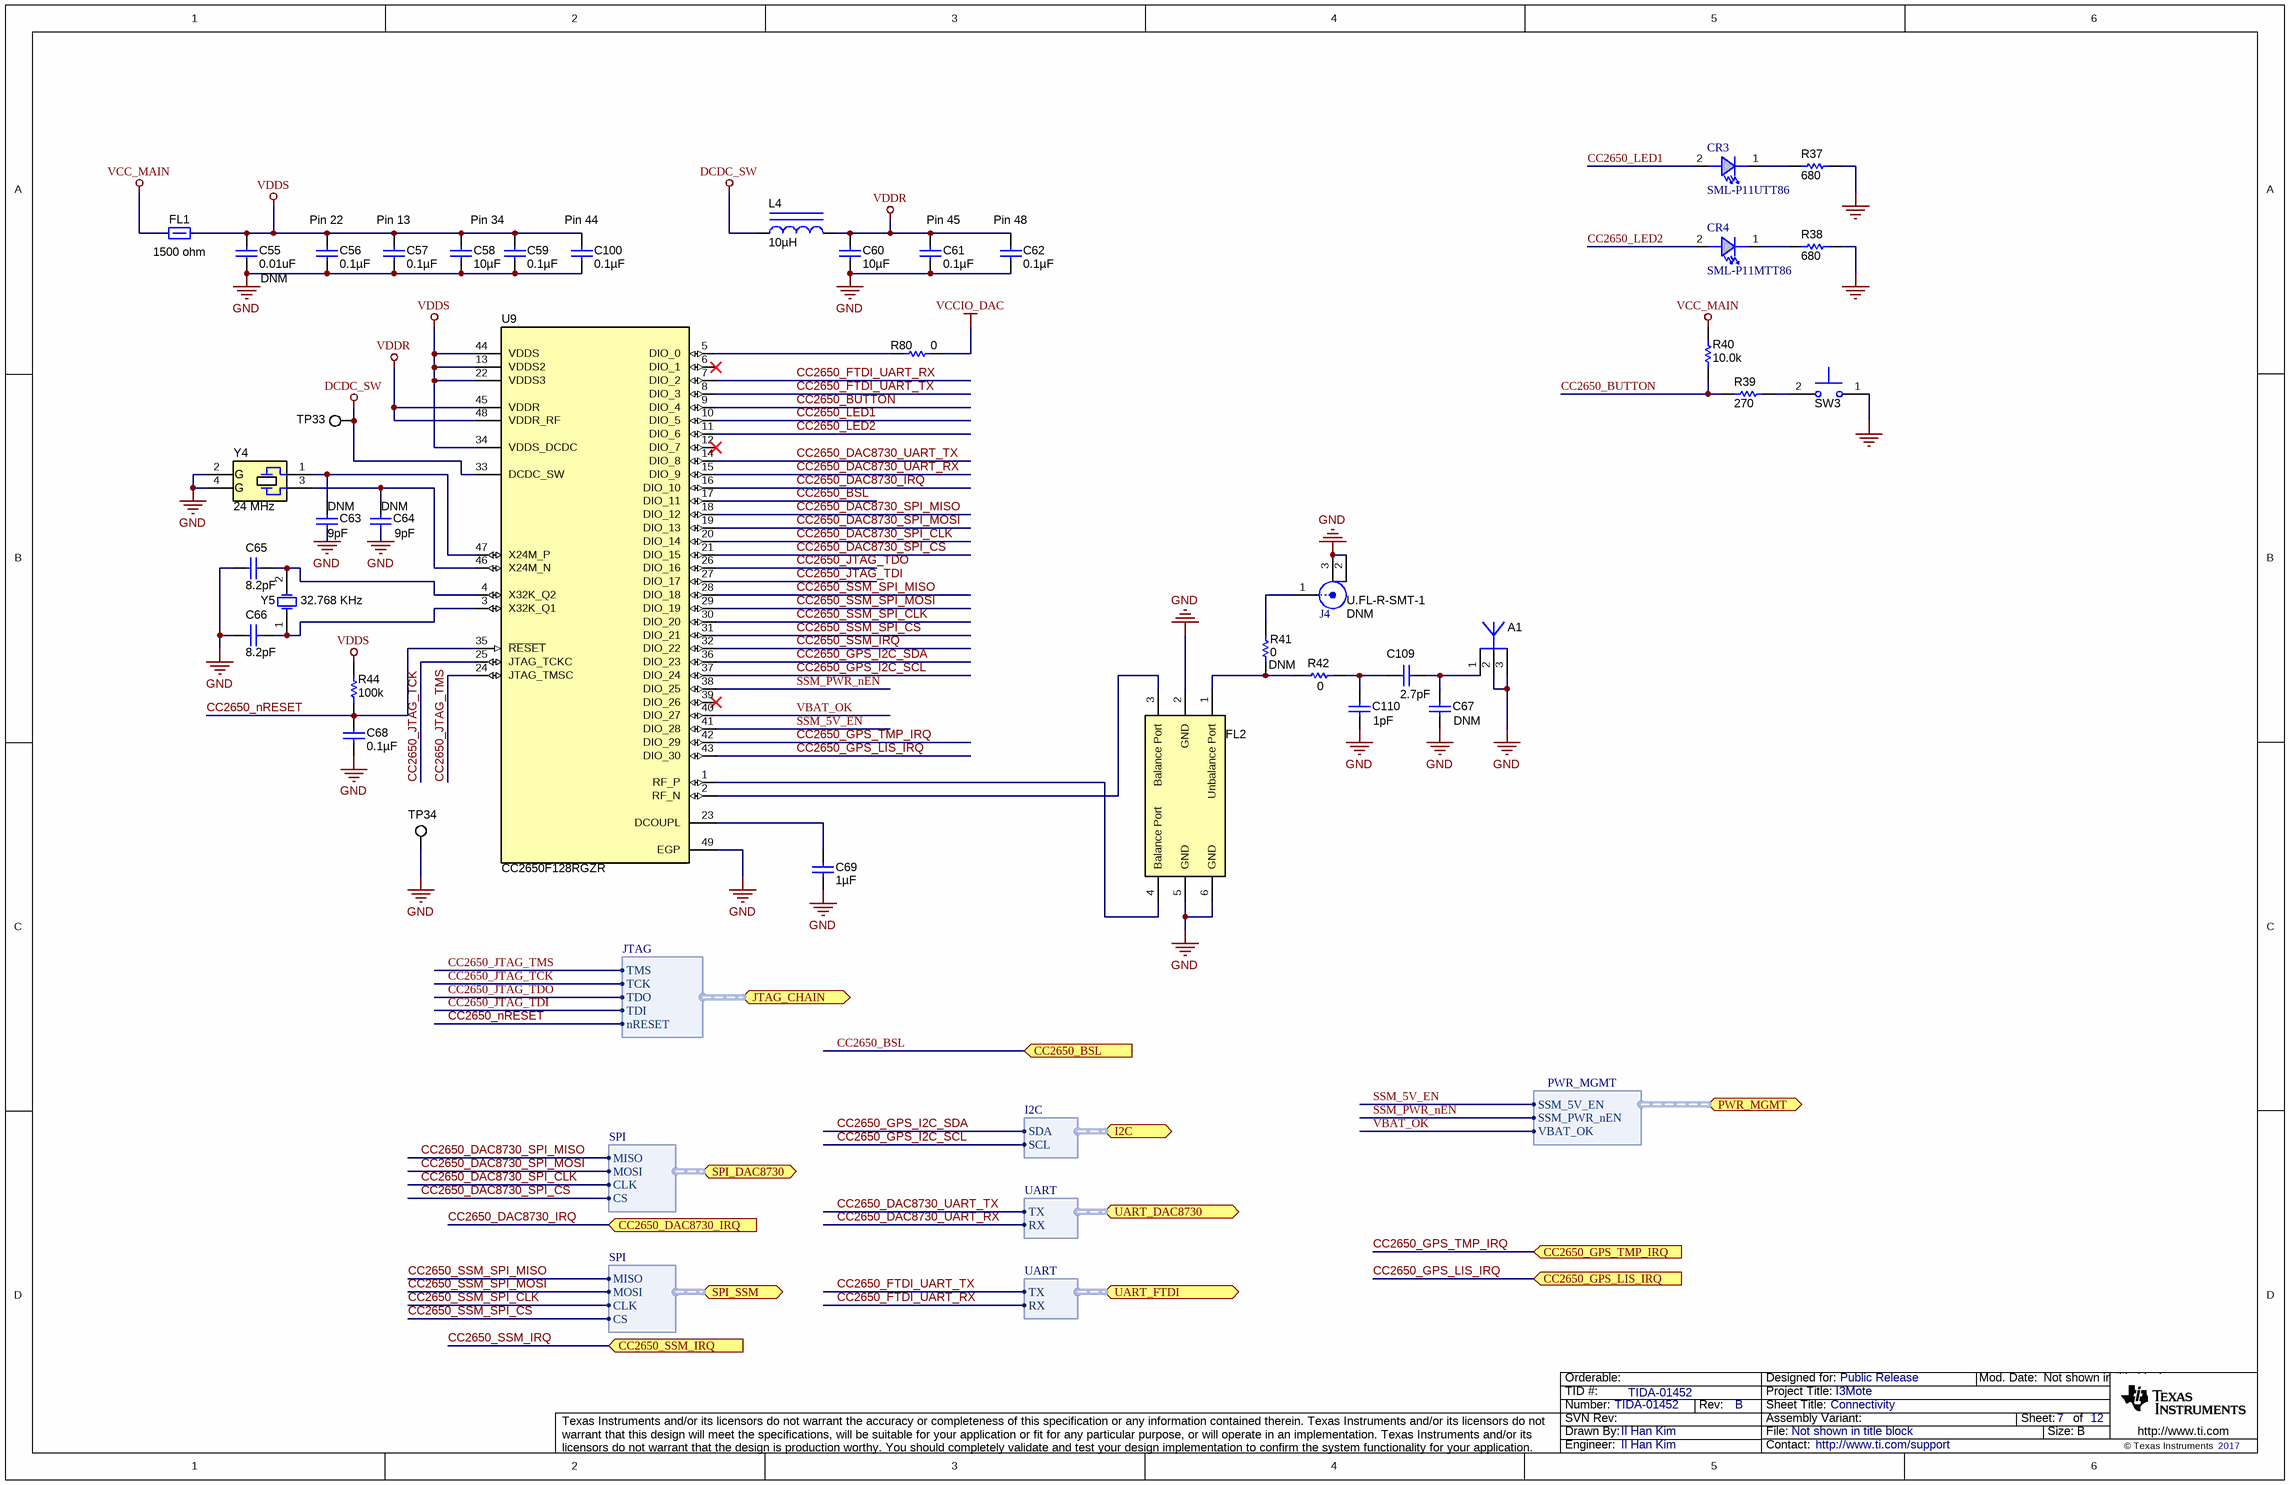
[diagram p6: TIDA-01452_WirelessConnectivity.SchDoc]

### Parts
A1  ANTENNA_DN007A  [ANTENNA_DN007A]  (value not drawn)  (net tie, no BOM)
C55  DNM  ValueDisplayed: 0.01uF  [0402]
C56  ValueDisplayed: 0.1µF  [0402]  (hidden comment: GRM155R70J104KA01D)
C57  ValueDisplayed: 0.1µF  [0402]  (hidden comment: GRM155R70J104KA01D)
C58  ValueDisplayed: 10µF  [0603]  (hidden comment: GRM188R60J106ME47D)
C59  ValueDisplayed: 0.1µF  [0402]  (hidden comment: GRM155R70J104KA01D)
C60  ValueDisplayed: 10µF  [0603]  (hidden comment: GRM188R60J106ME47D)
C61  ValueDisplayed: 0.1µF  [0402]  (hidden comment: GRM155R70J104KA01D)
C62  ValueDisplayed: 0.1µF  [0402]  (hidden comment: GRM155R70J104KA01D)
C63  DNM  ValueDisplayed: 9pF  [0402]
C64  DNM  ValueDisplayed: 9pF  [0402]
C65  ValueDisplayed: 8.2pF  [0402]  (hidden comment: GRM1555C1H8R2CA01D)
C66  ValueDisplayed: 8.2pF  [0402]  (hidden comment: GRM1555C1H8R2CA01D)
C67  DNM  [0402]
C68  ValueDisplayed: 0.1µF  [0402]  (hidden comment: GCM155R71H104KE02D)
C69  ValueDisplayed: 1µF  [0402]  (hidden comment: GRM155R61E105KA12D)
C100  ValueDisplayed: 0.1µF  [0402]  (hidden comment: GRM155R70J104KA01D)
C109  ValueDisplayed: 2.7pF  [0402]  (hidden comment: GRM1555C1H2R7CA01D)
C110  value 1pF  [0402]  (hidden comment: GRM1555C1H1R0CA01D)
CR3  SML-P11UTT86  [LEDC1708X67L]
CR4  SML-P11MTT86  [LEDC1707X65L]
FL1  value 1500 ohm  [0603]  (hidden comment: BLM18HE152SN1D)
FL2  LFB182G45BG5D920  [Murata_LFB182G45BG5D920]  (value not drawn)
J4  DNM  [CONN_UFL-R-SMT-1]
L4  ValueDisplayed: 10µH  [0805_145]  (hidden comment: CKS2125100M-T)
R37  ValueDisplayed: 680  [0402]  (hidden comment: CRCW0402680RJNED)
R38  ValueDisplayed: 680  [0402]  (hidden comment: CRCW0402680RJNED)
R39  ValueDisplayed: 270  [0402]  (hidden comment: CRCW0402270RFKED)
R40  ValueDisplayed: 10.0k  [0402]  (hidden comment: CRCW040210K0FKED)
R41  DNM  ValueDisplayed: 0  [0402]
R42  ValueDisplayed: 0  [0402]  (hidden comment: CRCW04020000Z0ED)
R44  ValueDisplayed: 100k  [0402]  (hidden comment: CRCW0402100KFKED)
R80  ValueDisplayed: 0  [0402]  (hidden comment: CRCW04020000Z0ED)
SW3  B3U-1000P  [SW_B3U-1000P]  (value not drawn)
TP33  NA  [TPS0.8]  (value not drawn)  (no BOM)
TP34  NA  [TPS0.8]  (value not drawn)  (no BOM)
U9  CC2650F128RGZR  [RGZ0048A]
Y4  Frequency: 24 MHz  [EPSON_TSX-3225]  (hidden comment: TSX-3225 24.0000MF20G-AC3)
Y5  Frequency: 32.768 KHz  [Epson_FC-135]  (hidden comment: FC-135 32.7680KA-AG0)

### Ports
CC2650_BSL (in), CC2650_DAC8730_IRQ (in), CC2650_GPS_LIS_IRQ (in), CC2650_GPS_TMP_IRQ (in), CC2650_SSM_IRQ (in), I2C (harness I2C), JTAG_CHAIN (harness JTAG), PWR_MGMT (harness PWR_MGMT), SPI_DAC8730 (harness SPI), SPI_SSM (harness SPI), UART_DAC8730 (harness UART), UART_FTDI (harness UART)

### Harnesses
SPI: MISO, MOSI, CLK, CS
SPI: CLK, CS, MISO, MOSI
I2C: SDA, SCL
UART: TX, RX
PWR_MGMT: SSM_5V_EN, VBAT_OK, SSM_PWR_nEN
JTAG: TMS, TCK, TDO, TDI, nRESET

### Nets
DCDC_SW: L4.1 TP33.1 U9.33(DCDC_SW)
GND: A1.2 A1.3 C55.2 C56.2 C57.2 C58.2 C59.2 C60.2 C61.2 C62.1 C63.2 C64.2 C65.2 C66.2 C67.2 C68.2 C69.2 C100.2 C110.2 FL2.2(GND) FL2.5(GND) FL2.6(GND) J4.2 J4.3 R37.1 R38.1 SW3.1 TP34.1 U9.49(EGP) Y4.2(GND) Y4.4(GND)
VCC_MAIN: FL1.1 R40.1
VCCIO_DAC: R80.2
VDDR: C60.1 C61.1 C62.2 L4.2 U9.45(VDDR) U9.48(VDDR_RF)
VDDS: C55.1 C56.1 C57.1 C58.1 C59.1 C100.1 FL1.2 R44.1 U9.13(VDDS2) U9.22(VDDS3) U9.34(VDDS_DCDC) U9.44(VDDS)
CC2650_BSL: U9.17(DIO_11) ; port CC2650_BSL
CC2650_BUTTON: R39.2 R40.2 U9.9(DIO_4)
CC2650_DAC8730_IRQ: U9.16(DIO_10) ; port CC2650_DAC8730_IRQ
CC2650_DAC8730_SPI_CLK: U9.20(DIO_14) ; port SPI_DAC8730.CLK
CC2650_DAC8730_SPI_CS: U9.21(DIO_15) ; port SPI_DAC8730.CS
CC2650_DAC8730_SPI_MISO: U9.18(DIO_12) ; port SPI_DAC8730.MISO
CC2650_DAC8730_SPI_MOSI: U9.19(DIO_13) ; port SPI_DAC8730.MOSI
CC2650_DAC8730_UART_RX: U9.15(DIO_9) ; port UART_DAC8730.RX
CC2650_DAC8730_UART_TX: U9.14(DIO_8) ; port UART_DAC8730.TX
CC2650_FTDI_UART_RX: U9.7(DIO_2) ; port UART_FTDI.RX
CC2650_FTDI_UART_TX: U9.8(DIO_3) ; port UART_FTDI.TX
CC2650_GPS_I2C_SCL: U9.37(DIO_24) ; port I2C.SCL
CC2650_GPS_I2C_SDA: U9.36(DIO_23) ; port I2C.SDA
CC2650_GPS_LIS_IRQ: U9.43(DIO_30) ; port CC2650_GPS_LIS_IRQ
CC2650_GPS_TMP_IRQ: U9.42(DIO_29) ; port CC2650_GPS_TMP_IRQ
CC2650_JTAG_TCK: U9.25(JTAG_TCKC) ; port JTAG_CHAIN.TCK
CC2650_JTAG_TDI: U9.27(DIO_17) ; port JTAG_CHAIN.TDI
CC2650_JTAG_TDO: U9.26(DIO_16) ; port JTAG_CHAIN.TDO
CC2650_JTAG_TMS: U9.24(JTAG_TMSC) ; port JTAG_CHAIN.TMS
CC2650_LED1: CR3.2(A) U9.10(DIO_5)
CC2650_LED2: CR4.2(A) U9.11(DIO_6)
CC2650_nRESET: C68.1 R44.2 U9.35(~{RESET}) ; port JTAG_CHAIN.nRESET
CC2650_SSM_IRQ: U9.32(DIO_22) ; port CC2650_SSM_IRQ
CC2650_SSM_SPI_CLK: U9.30(DIO_20) ; port SPI_SSM.CLK
CC2650_SSM_SPI_CS: U9.31(DIO_21) ; port SPI_SSM.CS
CC2650_SSM_SPI_MISO: U9.28(DIO_18) ; port SPI_SSM.MISO
CC2650_SSM_SPI_MOSI: U9.29(DIO_19) ; port SPI_SSM.MOSI
SSM_5V_EN: U9.41(DIO_28) ; port PWR_MGMT.SSM_5V_EN  [project net PWR_MGMT.SSM_5V_EN]
SSM_PWR_nEN: U9.38(DIO_25) ; port PWR_MGMT.SSM_PWR_nEN  [project net PWR_MGMT.SSM_PWR_nEN]
VBAT_OK: U9.40(DIO_27) ; port PWR_MGMT.VBAT_OK  [project net BQ25505_VBAT_OK]
NetA1_1: A1.1 C67.1 C109.1
NetC63_1: C63.1 U9.47(X24M_P) Y4.1
NetC64_1: C64.1 U9.46(X24M_N) Y4.3
NetC65_1: C65.1 U9.4(X32K_Q2) Y5.2(OSC2)
NetC66_1: C66.1 U9.3(X32K_Q1) Y5.1(OSC1)
NetC69_1: C69.1 U9.23(DCOUPL)
NetC109_2: C109.2 C110.1 R42.2
NetCR3_1: CR3.1(C) R37.2
NetCR4_1: CR4.1(C) R38.2
NetFL2_1: FL2.1(Unbalance_Port) R41.1 R42.1
NetFL2_3: FL2.3(Balance_Port) U9.2(RF_N)
NetFL2_4: FL2.4(Balance_Port) U9.1(RF_P)
NetJ4_1: J4.1 R41.2
NetR39_1: R39.1 SW3.2
NetR80_1: R80.1 U9.5(DIO_0)

Not connected (* = marked no-connect by the designer): U9 6(DIO_1)* 12(DIO_7)* 39(DIO_26)*

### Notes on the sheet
- (near C56) Pin 22
- (near C57) Pin 13
- Pin 34
- (near C100) Pin 44
- (near C61) Pin 45
- (near C62) Pin 48

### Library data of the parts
A1 = ANTENNA_DN007A: 2.4GHz PCB Antenna.  There is nothing to buy or mount.; SymbolCreator: a0412235
C55 C67 = C0402C103J5RACTU: CAP, CERM, 0.01 µF, 50 V, +/- 5%, X7R, 0402; Manufacturer: Kemet; Polarized: N; CompType: Capacitor; Value: 0.01uF; U/M: EA; Cap_F: 0.00000001; Tolerance_%: 5; Value1: Unknown; VDC_V: 50; Value2: 50V; TaMin_C: -55; TaMax_C: 125; SizeArea_mm2: 0.5; SizeAreaWB_mm2: 3; SizeX_mm: 1; SizeZ_mm: 0.6; AEC Category: Q200
C56 C57 C59 C61 C62 C100 = GRM155R70J104KA01D: CAP, CERM, 0.1 µF, 6.3 V, +/- 10%, X7R, 0402; Manufacturer: MuRata; Polarized: N; CompType: Capacitor; Value: 0.1uF; U/M: EA; Cap_F: 0.0000001; Tolerance_%: 10; Value1: Unknown; VDC_V: 6.3; Value2: 6.3V; TaMin_C: -55; TaMax_C: 125; SizeArea_mm2: 0.5; SizeAreaWB_mm2: 3; SizeX_mm: 1; SizeZ_mm: 0.6; AEC Category: Q200
C58 C60 = GRM188R60J106ME47D: CAP, CERM, 10 µF, 6.3 V, +/- 20%, X5R, 0603; Manufacturer: MuRata; Polarized: N; CompType: Capacitor; Value: 10uF; U/M: EA; Cap_F: 0.00001; Tolerance_%: 20; ESR_ohm: 0.009; Value1: 0.009 ohm; VDC_V: 6.3; Value2: 6.3V; IRMS_A: 2.74; TaMin_C: -55; TaMax_C: 125; SizeArea_mm2: 1.28; SizeAreaWB_mm2: 4.68; SizeX_mm: 1.6; SizeY_mm: 0.8; SizeZ_mm: 1; AEC Category: Q200
C63 C64 = GRM1555C1H9R0DA01D: CAP, CERM, 9pF, 50V, +/- 0.5pF, C0G/NP0, 0402; Manufacturer: MuRata; CompType: Capacitor; VDC_V: 50
C65 C66 = GRM1555C1H8R2CA01D: CAP, CERM, 8.2 pF, 50 V, +/- 5%, C0G/NP0, 0402; Manufacturer: MuRata; Polarized: N; CompType: Capacitor; Value: 8.2pF; U/M: EA; Cap_F: 0.0000000000082; Tolerance_%: 5; Value1: Unknown; VDC_V: 50; Value2: 50V; TaMin_C: -55; TaMax_C: 125; SizeArea_mm2: 0.5; SizeAreaWB_mm2: 3; SizeX_mm: 1; SizeZ_mm: 0.6; AEC Category: Q200
C68 = GCM155R71H104KE02D: as C5 on sheet TIDA-01452_Hart
C69 = GRM155R61E105KA12D: as C25 on sheet TIDA-01452_Hart
C109 = GRM1555C1H2R7CA01D: CAP, CERM, 2.7 pF, 50 V, +/- 5%, C0G/NP0, 0402; Manufacturer: MuRata; Polarized: N; CompType: Capacitor; Value: 2.7pF; U/M: EA; Cap_F: 0.0000000000027; Tolerance_%: 5; Value1: Unknown; VDC_V: 50; Value2: 50V; TaMin_C: -55; TaMax_C: 125; SizeArea_mm2: 0.5; SizeAreaWB_mm2: 3; SizeX_mm: 1; SizeZ_mm: 0.6; AEC Category: Q200
C110 = GRM1555C1H1R0CA01D: CAP, CERM, 1 pF, 50 V, +/- 5%, C0G/NP0, 0402; Manufacturer: MuRata; Polarized: N; CompType: Capacitor; U/M: EA; Cap_F: 0.000000000001; Tolerance_%: 5; Value1: Unknown; VDC_V: 50; Value2: 50V; TaMin_C: -55; TaMax_C: 125; SizeArea_mm2: 0.5; SizeAreaWB_mm2: 3; SizeX_mm: 1; SizeZ_mm: 0.6; AEC Category: Q200
CR3 = SML-P11UTT86: Red 621nm LED Indication - Discrete 1.8V 0402 (1005 Metric); Manufacturer: Rohm Semiconductor; PCB Package: 0402
CR4 = SML-P11MTT86: Green 569nm LED Indication - Discrete 1.9V 0402 (1005 Metric); Manufacturer: Rohm Semiconductor; PCB Package: 0402
FL1 = BLM18HE152SN1D: Ferrite Bead, 1500 ohm @ 100 MHz, 0.5 A, 0603; Manufacturer: MuRata; Imax_A: 0.5; Value1: 0.5 ohm; Value2: 0.5A; ZTyp@100MHz_Ohm: 1500
FL2 = LFB182G45BG5D920: Filter, BandPass, 2.45GHz, SMD; Manufacturer: MuRata; SymbolCreator: Altium
J4 = U.FL-R-SMT-1: Connector, Ultra-Mini Coaxial, SMD; Manufacturer: Hirose Electric Co. Ltd.; SymbolCreator: a0412235
L4 = CKS2125100M-T: Inductor, Multilayer, Ferrite, 10 µH, 0.11 A, 0.52 ohm, SMD; Manufacturer: Taiyo Yuden; Value: 10uH; Ind_H: 10.0E-6; Imax_A: 0.11; DCR_ohm: 0.52; Value2: 0.11A; AEC Category: Q200
R37 R38 = CRCW0402680RJNED: RES, 680, 5%, 0.063 W, 0402; Manufacturer: Vishay-Dale; Value: 680; CompType: Resistor; Value_Code: 680R; Tolerance_%: 5; Power_W: 0.063; Value2: 0.063W; VDC_V: 50; TempCo: 200 ppm/C; EIA_Code: E24; U/M: EA; AEC Category: Q200
R39 = CRCW0402270RFKED: RES, 270, 1%, 0.0625W, 50V, 0402; Manufacturer: Vishay-Dale; Value: 270
R40 = CRCW040210K0FKED: RES, 10.0 k, 1%, 0.063 W, 0402; Manufacturer: Vishay-Dale; CompType: Resistor; Value: 10.0k; Res_ohm: 10000; Value_Code: 10k0; Tolerance_%: 1; Power_W: 0.063; Value2: 0.063W; VDC_V: 50; TempCo: 100 ppm/C; EIA_Code: E96; U/M: EA; AEC Category: Q200
R41 R42 R80 = CRCW04020000Z0ED: as R26 on sheet TIDA-01452_Hart
R44 = CRCW0402100KFKED: as R7 on sheet TIDA-01452_Hart
SW3 = B3U-1000P: SWITCH TACTILE SPST-NO 0.05A 12V; Manufacturer: Omron Electronic Components; SymbolCreator: a0412235; VDC_V: 12; SwitchFunction: Off-Mom; PositionCount: 1; CurrentRating_mA: 50
TP33 TP34 = TEST_POINT_ROUND_1.2: Round Test Point, 1.2mm diam.
U9 = CC2650F128RGZR: SimpleLink Multistandard Wireless MCU, RGZ0048A; Alternate PartNumber: CC2650F128RGZT; Manufacturer: Texas Instruments; SymbolCreator: a0412235; SizeArea_mm2: 49; SizeX_mm: 7; SizeZ_mm: 1; CompType: IC; U/M: EA
Y4 = TSX-3225 24.0000MF20G-AC3: Crystal, 24 MHz, 9 pF, SMD; Manufacturer: Epson; SymbolCreator: a0412235; U/M: EA; TaMin_C: -40; TaMax_C: 85; Frequency Stability: ±20ppm
Y5 = FC-135 32.7680KA-AG0: Crystal, 32.768 KHz, 7 pF, SMD; Manufacturer: Epson; U/M: EA; TaMin_C: -40; TaMax_C: 85; Frequency Tolerance: ±20ppm

## Sheet TIDA-01452_DataFusion.SchDoc: DataFusion
size 431 x 279 mm; Date: Not shown in title block; ApprovedBy: Not shown in title block; CheckedBy: Not shown in title block; Author: Not shown in title block; CompanyName: Not shown in title block; DrawnBy: Il Han Kim; Engineer: Not shown in title block; Organization: Not shown in title block; Address1: Not shown in title block; Address2: Not shown in title block; Address3: Not shown in title block; Address4: Not shown in title block; DocumentNumber: 4; Revision: Use project parameter SCH_Rev; SheetNumber: 5; SheetTotal: 12; PageSetup: Record=PageOptions¦CenterHorizontal=True¦CenterVertical=True¦PrintScale=0.96¦XCorrection=1.00¦YCorrection=1.00¦PrintKind=0¦BorderSize=5000000¦LeftOffset=0¦BottomOffset=0¦Orientation=2¦PaperLength=1000¦PaperWidth=1000¦Scale=100¦PaperSource=15¦PrintQuality=-3¦MediaType=1¦DitherType=10¦PrintScaleMode=1¦PaperKind=A3¦PaperIndex=8
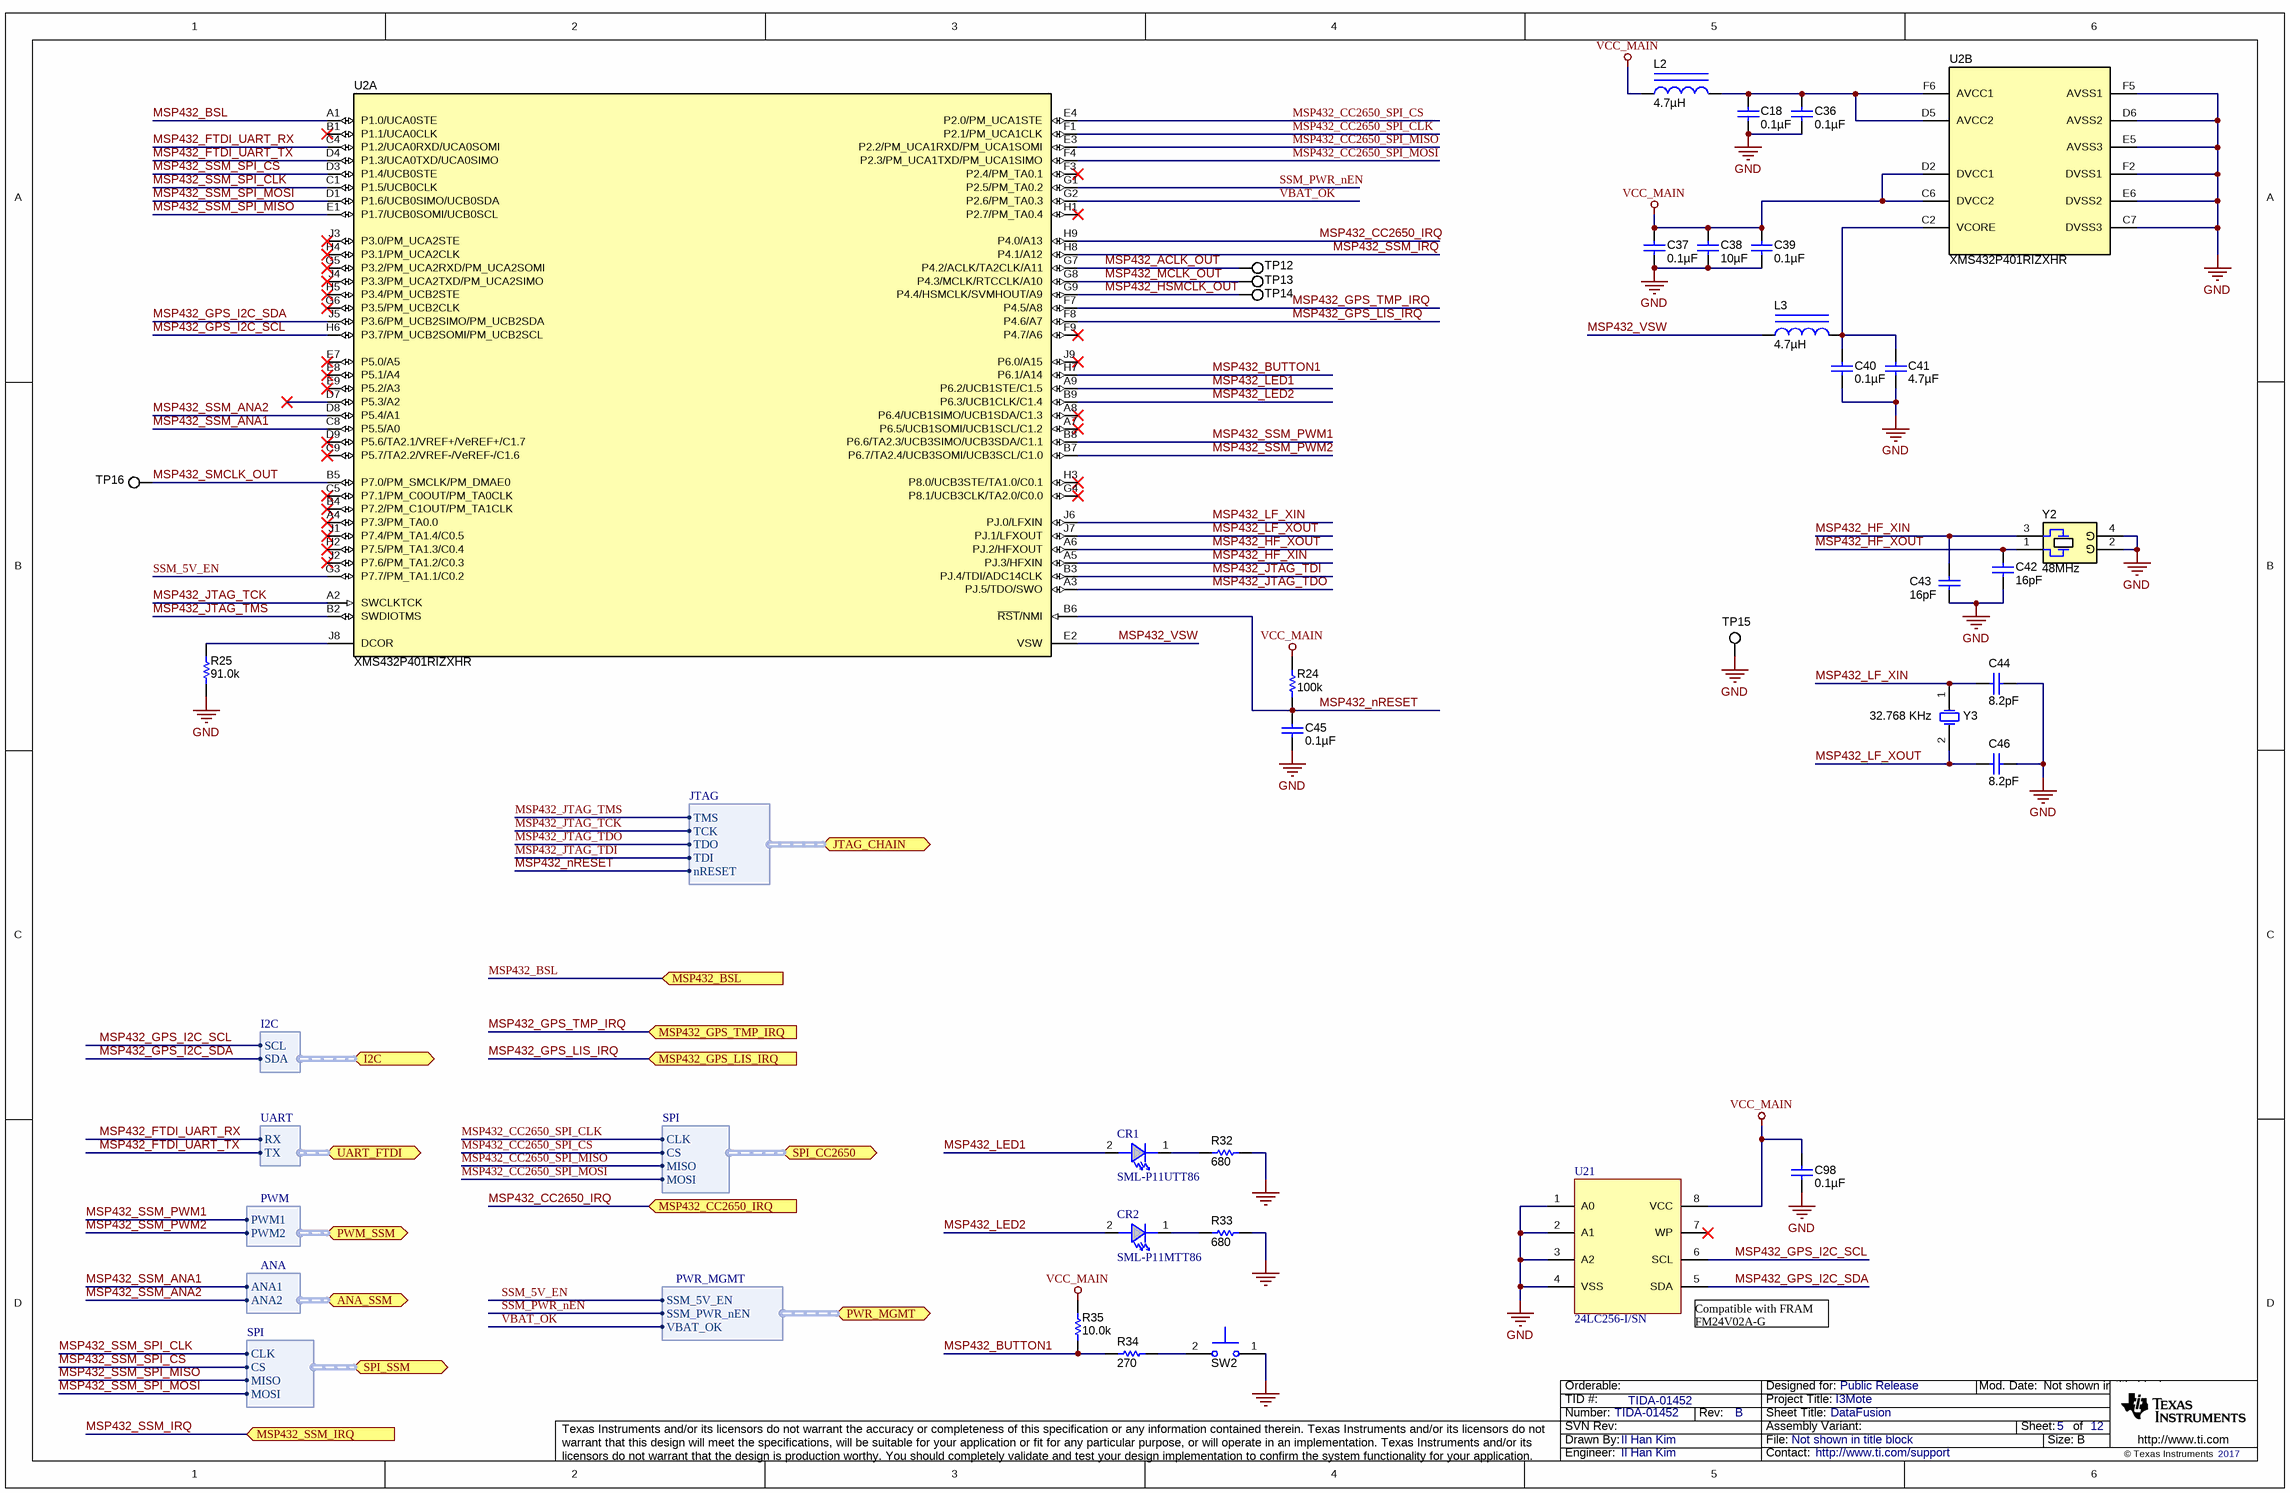
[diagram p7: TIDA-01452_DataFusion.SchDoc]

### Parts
C18  ValueDisplayed: 0.1µF  [0402]  (hidden comment: GRM155R70J104KA01D)
C36  ValueDisplayed: 0.1µF  [0402]  (hidden comment: GRM155R70J104KA01D)
C37  ValueDisplayed: 0.1µF  [0402]  (hidden comment: GRM155R70J104KA01D)
C38  ValueDisplayed: 10µF  [0603]  (hidden comment: GRM188R60J106ME47D)
C39  ValueDisplayed: 0.1µF  [0402]  (hidden comment: GRM155R70J104KA01D)
C40  ValueDisplayed: 0.1µF  [0402]  (hidden comment: GRM155R70J104KA01D)
C41  ValueDisplayed: 4.7µF  [0402]  (hidden comment: C1005X5R1A475K050BC)
C42  ValueDisplayed: 16pF  [0402]  (hidden comment: GRM1555C1H160JA01D)
C43  ValueDisplayed: 16pF  [0402]  (hidden comment: GRM1555C1H160JA01D)
C44  ValueDisplayed: 8.2pF  [0402]  (hidden comment: GRM1555C1H8R2CA01D)
C45  ValueDisplayed: 0.1µF  [0402]  (hidden comment: GCM155R71H104KE02D)
C46  ValueDisplayed: 8.2pF  [0402]  (hidden comment: GRM1555C1H8R2CA01D)
C98  ValueDisplayed: 0.1µF  [0402]  (hidden comment: GRM155R70J104KA01D)
CR1  SML-P11UTT86  [LEDC1708X67L]
CR2  SML-P11MTT86  [LEDC1707X65L]
L2  ValueDisplayed: 4.7µH  [MLP2520S-S]  (hidden comment: MLP2520S4R7ST0S1)
L3  ValueDisplayed: 4.7µH  [MLP2520S-S]  (hidden comment: MLP2520S4R7ST0S1)
R24  ValueDisplayed: 100k  [0402]  (hidden comment: CRCW0402100KFKED)
R25  ValueDisplayed: 91.0k  [0603]  (hidden comment: RG1608P-913-B-T5)
R32  ValueDisplayed: 680  [0402]  (hidden comment: CRCW0402680RJNED)
R33  ValueDisplayed: 680  [0402]  (hidden comment: CRCW0402680RJNED)
R34  ValueDisplayed: 270  [0402]  (hidden comment: CRCW0402270RFKED)
R35  ValueDisplayed: 10.0k  [0402]  (hidden comment: CRCW040210K0FKED)
SW2  B3U-1000P  [SW_B3U-1000P]  (value not drawn)
TP12  NA  [TPS0.8]  (value not drawn)  (no BOM)
TP13  NA  [TPS0.8]  (value not drawn)  (no BOM)
TP14  NA  [TPS0.8]  (value not drawn)  (no BOM)
TP15  NA  [TPS0.8]  (value not drawn)  (no BOM)
TP16  NA  [TPS0.8]  (value not drawn)  (no BOM)
U2  XMS432P401RIZXHR  [ZXH0080A]  (parts A,B of 2)
U21  24LC256-I/SN  [D0008A_N]
Y2  Frequency: 48MHz  [HEC_X3S048000BG1H-U]  (hidden comment: 732-FA238-48B-K3)
Y3  Frequency: 32.768 KHz  [Epson_FC-135]  (hidden comment: FC-135 32.7680KA-AG0)

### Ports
ANA_SSM (harness ANA), I2C (harness I2C), JTAG_CHAIN (harness JTAG), MSP432_BSL (in), MSP432_CC2650_IRQ (in), MSP432_GPS_LIS_IRQ (in), MSP432_GPS_TMP_IRQ (in), MSP432_SSM_IRQ (in), PWM_SSM (harness PWM), PWR_MGMT (harness PWR_MGMT), SPI_CC2650 (harness SPI), SPI_SSM (harness SPI), UART_FTDI (harness UART)

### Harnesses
UART: RX, TX
SPI: CLK, CS, MISO, MOSI
PWR_MGMT: SSM_5V_EN, VBAT_OK, SSM_PWR_nEN
PWM: PWM1, PWM2
ANA: ANA1, ANA2
JTAG: TMS, TCK, TDO, TDI, nRESET
I2C: SCL, SDA

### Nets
GND: C18.2 C36.2 C37.2 C38.2 C39.2 C40.2 C41.2 C42.2 C43.2 C44.1 C45.2 C46.1 C98.2 R25.1 R32.1 R33.1 SW2.1 TP15.1 U2.C7(DVSS3) U2.D6(AVSS2) U2.E5(AVSS3) U2.E6(DVSS2) U2.F2(DVSS1) U2.F5(AVSS1) U21.1(A0) U21.2(A1) U21.3(A2) U21.4(VSS) Y2.2(GND) Y2.4(GND)
VCC_MAIN: C37.1 C38.1 C39.1 C98.1 L2.1 R24.1 R35.1 U2.C6(DVCC2) U2.D2(DVCC1) U21.8(VCC)
MSP432_ACLK_OUT: TP12.1 U2.G7(P4.2/ACLK/TA2CLK/A11)
MSP432_BSL: U2.A1(P1.0/UCA0STE) ; port MSP432_BSL
MSP432_BUTTON1: R34.2 R35.2 U2.H7(P6.1/A14)
MSP432_CC2650_IRQ: U2.H9(P4.0/A13) ; port MSP432_CC2650_IRQ  [project net CC2650_SSM_IRQ]
MSP432_CC2650_SPI_CLK: U2.F1(P2.1/PM_UCA1CLK) ; port SPI_CC2650.CLK  [project net CC2650_SSM_SPI_CLK]
MSP432_CC2650_SPI_CS: U2.E4(P2.0/PM_UCA1STE) ; port SPI_CC2650.CS  [project net CC2650_SSM_SPI_CS]
MSP432_CC2650_SPI_MISO: U2.E3(P2.2/PM_UCA1RXD/PM_UCA1SOMI) ; port SPI_CC2650.MISO  [project net CC2650_SSM_SPI_MISO]
MSP432_CC2650_SPI_MOSI: U2.F4(P2.3/PM_UCA1TXD/PM_UCA1SIMO) ; port SPI_CC2650.MOSI  [project net CC2650_SSM_SPI_MOSI]
MSP432_FTDI_UART_RX: U2.C4(P1.2/UCA0RXD/UCA0SOMI) ; port UART_FTDI.RX  [project net FTDI_UART1.TX]
MSP432_FTDI_UART_TX: U2.D4(P1.3/UCA0TXD/UCA0SIMO) ; port UART_FTDI.TX  [project net FTDI_UART1.RX]
MSP432_GPS_I2C_SCL: U2.H6(P3.7/PM_UCB2SOMI/PM_UCB2SCL) U21.6(SCL) ; port I2C.SCL  [project net CC2650_GPS_I2C_SCL]
MSP432_GPS_I2C_SDA: U2.J5(P3.6/PM_UCB2SIMO/PM_UCB2SDA) U21.5(SDA) ; port I2C.SDA  [project net CC2650_GPS_I2C_SDA]
MSP432_GPS_LIS_IRQ: U2.F8(P4.6/A7) ; port MSP432_GPS_LIS_IRQ  [project net CC2650_GPS_LIS_IRQ]
MSP432_GPS_TMP_IRQ: U2.F7(P4.5/A8) ; port MSP432_GPS_TMP_IRQ  [project net CC2650_GPS_TMP_IRQ]
MSP432_HF_XIN: C43.1 U2.A5(PJ.3/HFXIN) Y2.3
MSP432_HF_XOUT: C42.1 U2.A6(PJ.2/HFXOUT) Y2.1
MSP432_HSMCLK_OUT: TP14.1 U2.G9(P4.4/HSMCLK/SVMHOUT/A9)
MSP432_JTAG_TCK: U2.A2(SWCLKTCK) ; port JTAG_CHAIN.TCK
MSP432_JTAG_TDI: U2.B3(PJ.4/TDI/ADC14CLK) ; port JTAG_CHAIN.TDI  [project net CC2650_JTAG_TDO]
MSP432_JTAG_TDO: U2.A3(PJ.5/TDO/SWO) ; port JTAG_CHAIN.TDO  [project net JTAG_TDO]
MSP432_JTAG_TMS: U2.B2(SWDIOTMS) ; port JTAG_CHAIN.TMS  [project net CC2650_JTAG_TMS]
MSP432_LED1: CR1.2(A) U2.A9(P6.2/UCB1STE/C1.5)
MSP432_LED2: CR2.2(A) U2.B9(P6.3/UCB1CLK/C1.4)
MSP432_LF_XIN: C44.2 U2.J6(PJ.0/LFXIN) Y3.1(OSC1)
MSP432_LF_XOUT: C46.2 U2.J7(PJ.1/LFXOUT) Y3.2(OSC2)
MSP432_MCLK_OUT: TP13.1 U2.G8(P4.3/MCLK/RTCCLK/A10)
MSP432_nRESET: C45.1 R24.2 U2.B6(~{RST}/NMI) ; port JTAG_CHAIN.nRESET  [project net CC2650_nRESET]
MSP432_SMCLK_OUT: TP16.1 U2.B5(P7.0/PM_SMCLK/PM_DMAE0)
MSP432_SSM_ANA1: U2.C8(P5.5/A0) ; port ANA_SSM.ANA1  [project net ANA_SSM.ANA1]
MSP432_SSM_ANA2: U2.D8(P5.4/A1) ; port ANA_SSM.ANA2  [project net ANA_SSM.ANA2]
MSP432_SSM_IRQ: U2.H8(P4.1/A12) ; port MSP432_SSM_IRQ  [project net IRQ_MSP432_SSM]
MSP432_SSM_PWM1: U2.B8(P6.6/TA2.3/UCB3SIMO/UCB3SDA/C1.1) ; port PWM_SSM.PWM1
MSP432_SSM_PWM2: U2.B7(P6.7/TA2.4/UCB3SOMI/UCB3SCL/C1.0) ; port PWM_SSM.PWM2
MSP432_SSM_SPI_CLK: U2.C1(P1.5/UCB0CLK) ; port SPI_SSM.CLK
MSP432_SSM_SPI_CS: U2.D3(P1.4/UCB0STE) ; port SPI_SSM.CS
MSP432_SSM_SPI_MISO: U2.E1(P1.7/UCB0SOMI/UCB0SCL) ; port SPI_SSM.MISO
MSP432_SSM_SPI_MOSI: U2.D1(P1.6/UCB0SIMO/UCB0SDA) ; port SPI_SSM.MOSI
MSP432_VSW: L3.1 U2.E2(VSW)
SSM_5V_EN: U2.G3(P7.7/PM_TA1.1/C0.2) ; port PWR_MGMT.SSM_5V_EN  [project net PWR_MGMT.SSM_5V_EN]
SSM_PWR_nEN: U2.G1(P2.5/PM_TA0.2) ; port PWR_MGMT.SSM_PWR_nEN  [project net PWR_MGMT.SSM_PWR_nEN]
VBAT_OK: U2.G2(P2.6/PM_TA0.3) ; port PWR_MGMT.VBAT_OK  [project net BQ25505_VBAT_OK]
NetC18_1: C18.1 C36.1 L2.2 U2.D5(AVCC2) U2.F6(AVCC1)
NetC40_1: C40.1 C41.1 L3.2 U2.C2(VCORE)
NetCR1_1: CR1.1(C) R32.2
NetCR2_1: CR2.1(C) R33.2
NetR25_2: R25.2 U2.J8(DCOR)
NetR34_1: R34.1 SW2.2

Not connected (* = marked no-connect by the designer): U2 A4(P7.3/PM_TA0.0)* A7(P6.5/UCB1SOMI/UCB1SCL/C1.2)* A8(P6.4/UCB1SIMO/UCB1SDA/C1.3)* B1(P1.1/UCA0CLK)* B4(P7.2/PM_C1OUT/PM_TA1CLK)* C5(P7.1/PM_C0OUT/PM_TA0CLK)* C9(P5.7/TA2.2/VREF-/VeREF-/C1.6)* D7(P5.3/A2)* D9(P5.6/TA2.1/VREF+/VeREF+/C1.7)* E7(P5.0/A5)* E8(P5.1/A4)* E9(P5.2/A3)* F3(P2.4/PM_TA0.1)* F9(P4.7/A6)* G4(P8.1/UCB3CLK/TA2.0/C0.0)* G5(P3.2/PM_UCA2RXD/PM_UCA2SOMI)* G6(P3.5/PM_UCB2CLK)* H1(P2.7/PM_TA0.4)* H2(P7.5/PM_TA1.3/C0.4)* H3(P8.0/UCB3STE/TA1.0/C0.1)* H4(P3.1/PM_UCA2CLK)* H5(P3.4/PM_UCB2STE)* J1(P7.4/PM_TA1.4/C0.5)* J2(P7.6/PM_TA1.2/C0.3)* J3(P3.0/PM_UCA2STE)* J4(P3.3/PM_UCA2TXD/PM_UCA2SIMO)* J9(P6.0/A15)*; U21 7(WP)*

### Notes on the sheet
- (near U21) Compatible with FRAM FM24V02A-G

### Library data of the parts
C18 C36 C37 C39 C40 C98 = GRM155R70J104KA01D: as C56 on sheet TIDA-01452_WirelessConnectivity
C38 = GRM188R60J106ME47D: as C58 on sheet TIDA-01452_WirelessConnectivity
C41 = C1005X5R1A475K050BC: CAP, CERM, 4.7 µF, 10 V, +/- 10%, X5R, 0402; Manufacturer: TDK; Polarized: N; CompType: Capacitor; Value: 4.7uF; U/M: EA; Cap_F: 0.0000047; Tolerance_%: 10; Value1: Unknown; Value2: 10V; TaMin_C: -55; TaMax_C: 85; AEC Category: Q200
C42 C43 = GRM1555C1H160JA01D: as C10 on sheet TIDA-01452_Hart
C44 C46 = GRM1555C1H8R2CA01D: as C65 on sheet TIDA-01452_WirelessConnectivity
C45 = GCM155R71H104KE02D: as C5 on sheet TIDA-01452_Hart
CR1 = SML-P11UTT86: as CR3 on sheet TIDA-01452_WirelessConnectivity
CR2 = SML-P11MTT86: as CR4 on sheet TIDA-01452_WirelessConnectivity
L2 L3 = MLP2520S4R7ST0S1: Inductor, Multilayer, Ferrite, 4.7 µH, 0.3 A, 0.143 ohm, SMD; Manufacturer: TDK; Value: 4.7uH; Ind_H: 4.7E-6; Imax_A: 0.3; Irms: 1.4A @ 40C rise; Isat: 0.3A @ 30% inductance drop; DCR_ohm: 0.143; Value2: 0.3A; AEC Category: Q200
R24 = CRCW0402100KFKED: as R7 on sheet TIDA-01452_Hart
R25 = RG1608P-913-B-T5: RES, 91.0 k, 0.1%, 0.1 W, 0603; Manufacturer: Susumu Co Ltd; CompType: Resistor; Value: 91.0k; Res_ohm: 91000; Value_Code: 91k0; Tolerance_%: 0.1; Value2: 0.1W; VDC_V: 75; TempCo: 25 ppm/C; SizeArea_mm2: 1.28; SizeX_mm: 1.6; SizeY_mm: 0.8; SizeZ_mm: 1; U/M: EA; AEC Category: Q200
R32 R33 = CRCW0402680RJNED: as R37 on sheet TIDA-01452_WirelessConnectivity
R34 = CRCW0402270RFKED: as R39 on sheet TIDA-01452_WirelessConnectivity
R35 = CRCW040210K0FKED: as R40 on sheet TIDA-01452_WirelessConnectivity
SW2 = B3U-1000P: as SW3 on sheet TIDA-01452_WirelessConnectivity
TP12-TP16 = TEST_POINT_ROUND_1.2: Round Test Point, 1.2mm diam.
U2 = XMS432P401RIZXHR: Mixed-Signal Microcontroller, ZXH0080A; Alternate PartNumber: XMS432P401RIZXHT; Manufacturer: Texas Instruments; SymbolCreator: Altium; SizeArea_mm2: 25; SizeAreaWB_mm2: 49; SizeX_mm: 5; SizeZ_mm: 1; CompType: IC; U/M: EA
U21 = 24LC256-I/SN: 256K I2C CMOS Serial EEPROM; Manufacturer: Microchip
Y2 = 732-FA238-48B-K3: Crystal, 48MHz, 10pF, SMD; Manufacturer: Epson
Y3 = FC-135 32.7680KA-AG0: as Y5 on sheet TIDA-01452_WirelessConnectivity

## Sheet TIDA-01452_SmartSensorIF.SchDoc: SmartSensorIF
size 431 x 279 mm; Date: Not shown in title block; ApprovedBy: Not shown in title block; CheckedBy: Not shown in title block; Author: Not shown in title block; CompanyName: Not shown in title block; DrawnBy: Il Han Kim; Engineer: Not shown in title block; Organization: Not shown in title block; Address1: Not shown in title block; Address2: Not shown in title block; Address3: Not shown in title block; Address4: Not shown in title block; DocumentNumber: 11; Revision: Use project parameter SCH_Rev; SheetNumber: 12; SheetTotal: 12; PageSetup: Record=PageOptions¦CenterHorizontal=True¦CenterVertical=True¦PrintScale=0.62¦XCorrection=1.00¦YCorrection=1.00¦PrintKind=0¦BorderSize=5000000¦LeftOffset=0¦BottomOffset=0¦Orientation=2¦PaperLength=1000¦PaperWidth=1000¦Scale=100¦PaperSource=15¦PrintQuality=600¦MediaType=1¦DitherType=10¦PrintScaleMode=1¦PaperKind=Letter
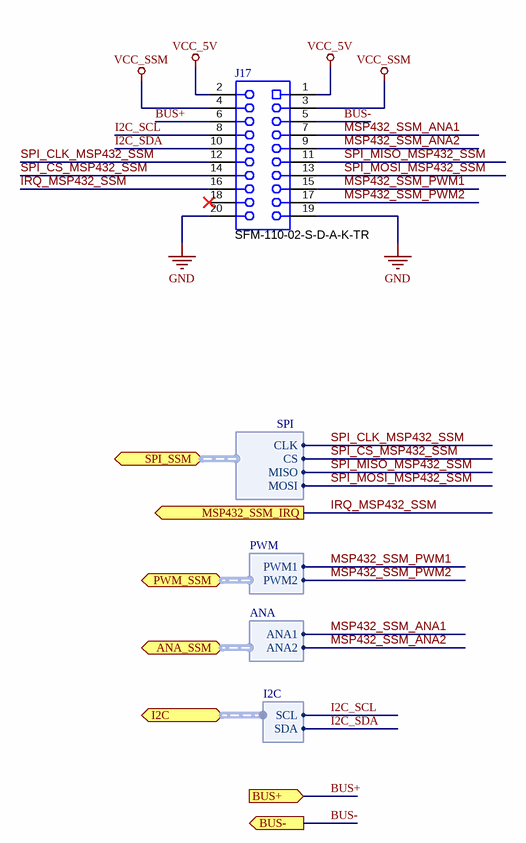
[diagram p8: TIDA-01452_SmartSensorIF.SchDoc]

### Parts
J17  SFM-110-02-S-D-A-K-TR  [Samtec_SFM-110-02-S-D-A-K]

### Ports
ANA_SSM (harness ANA), BUS+ (in), BUS- (out), I2C (harness I2C), MSP432_SSM_IRQ (out), PWM_SSM (harness PWM), SPI_SSM (harness SPI)

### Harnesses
SPI: CLK, CS, MISO, MOSI
PWM: PWM1, PWM2
ANA: ANA1, ANA2
I2C: SCL, SDA

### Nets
GND: J17.19 J17.20
VCC_5V: J17.1 J17.2
VCC_SSM: J17.3 J17.4
BUS+: J17.6 ; port BUS+
BUS-: J17.5 ; port BUS-
I2C_SCL: J17.8 ; port I2C.SCL  [project net CC2650_GPS_I2C_SCL]
I2C_SDA: J17.10 ; port I2C.SDA  [project net CC2650_GPS_I2C_SDA]
IRQ_MSP432_SSM: J17.16 ; port MSP432_SSM_IRQ
MSP432_SSM_ANA1: J17.7 ; port ANA_SSM.ANA1  [project net ANA_SSM.ANA1]
MSP432_SSM_ANA2: J17.9 ; port ANA_SSM.ANA2  [project net ANA_SSM.ANA2]
MSP432_SSM_PWM1: J17.15 ; port PWM_SSM.PWM1
MSP432_SSM_PWM2: J17.17 ; port PWM_SSM.PWM2
SPI_CLK_MSP432_SSM: J17.12 ; port SPI_SSM.CLK  [project net MSP432_SSM_SPI_CLK]
SPI_CS_MSP432_SSM: J17.14 ; port SPI_SSM.CS  [project net MSP432_SSM_SPI_CS]
SPI_MISO_MSP432_SSM: J17.11 ; port SPI_SSM.MISO  [project net MSP432_SSM_SPI_MISO]
SPI_MOSI_MSP432_SSM: J17.13 ; port SPI_SSM.MOSI  [project net MSP432_SSM_SPI_MOSI]

Not connected (* = marked no-connect by the designer): J17 18*

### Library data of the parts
J17 = SFM-110-02-S-D-A-K-TR: Receptacle, 50mil, 10x2, Gold, SMT; Manufacturer: Samtec; SymbolCreator: a0412235

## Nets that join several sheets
GND: TIDA-01452_I3Mote (J2.3 J2.5 J2.9 SW1.1), TIDA-01452_Sensors (21 pins), TIDA-01452_PowerManagement (22 pins), TIDA-01452_PWR_EH (28 pins), TIDA-01452_Hart (45 pins), TIDA-01452_DEBUG_USB (J18.2 J18.12), TIDA-01452_WirelessConnectivity (31 pins), TIDA-01452_DataFusion (30 pins), TIDA-01452_SmartSensorIF (J17.19 J17.20)
ISense-: TIDA-01452_PowerManagement (7 pins), TIDA-01452_DEBUG_USB (J18.1)
VCC_5V: TIDA-01452_PowerManagement (C75.1 R54.2 TP22.1 U12.4), TIDA-01452_SmartSensorIF (J17.1 J17.2)
VCC_GPS: TIDA-01452_Sensors (21 pins), TIDA-01452_PowerManagement (R96.1)
VCC_MAIN: TIDA-01452_I3Mote (R31.1 R109.1 R110.1), TIDA-01452_PowerManagement (7 pins), TIDA-01452_Hart (R29.1), TIDA-01452_DEBUG_USB (J18.11), TIDA-01452_WirelessConnectivity (FL1.1 R40.1), TIDA-01452_DataFusion (10 pins)
VCC_SSM: TIDA-01452_PowerManagement (R95.1 TP1.1 U22.4), TIDA-01452_SmartSensorIF (J17.3 J17.4)
VCCIO_DAC: TIDA-01452_PowerManagement (JP7.3), TIDA-01452_Hart (6 pins), TIDA-01452_WirelessConnectivity (R80.2)
ANA_SSM.ANA1: TIDA-01452_DataFusion (U2.C8), TIDA-01452_SmartSensorIF (J17.7)
ANA_SSM.ANA2: TIDA-01452_DataFusion (U2.D8), TIDA-01452_SmartSensorIF (J17.9)
BQ25505_VBAT_OK: TIDA-01452_PWR_EH (R60.1), TIDA-01452_WirelessConnectivity (U9.40), TIDA-01452_DataFusion (U2.G2)
BUS+: TIDA-01452_Hart (J5.2 JP24.1 R19.1), TIDA-01452_SmartSensorIF (J17.6)
BUS-: TIDA-01452_Hart (J5.1 JP25.1), TIDA-01452_SmartSensorIF (J17.5)
CC2650_BSL: TIDA-01452_DEBUG_USB (J18.10), TIDA-01452_WirelessConnectivity (U9.17)
CC2650_DAC8730_IRQ: TIDA-01452_Hart (R131.2 U1.26), TIDA-01452_WirelessConnectivity (U9.16)
CC2650_DAC8730_SPI_CLK: TIDA-01452_Hart (U1.29), TIDA-01452_WirelessConnectivity (U9.20)
CC2650_DAC8730_SPI_CS: TIDA-01452_Hart (R29.2 U1.32), TIDA-01452_WirelessConnectivity (U9.21)
CC2650_DAC8730_SPI_MISO: TIDA-01452_Hart (R28.2 U1.30), TIDA-01452_WirelessConnectivity (U9.18)
CC2650_DAC8730_SPI_MOSI: TIDA-01452_Hart (U1.31), TIDA-01452_WirelessConnectivity (U9.19)
CC2650_DAC8730_UART_RX: TIDA-01452_Hart (R132.2 U1.27), TIDA-01452_WirelessConnectivity (U9.15)
CC2650_DAC8730_UART_TX: TIDA-01452_Hart (U1.28), TIDA-01452_WirelessConnectivity (U9.14)
CC2650_FTDI_UART_RX: TIDA-01452_DEBUG_USB (J18.7), TIDA-01452_WirelessConnectivity (U9.7)
CC2650_FTDI_UART_TX: TIDA-01452_DEBUG_USB (J18.9), TIDA-01452_WirelessConnectivity (U9.8)
CC2650_GPS_I2C_SCL: TIDA-01452_I3Mote (R109.2), TIDA-01452_Sensors (R119.1), TIDA-01452_WirelessConnectivity (U9.37), TIDA-01452_DataFusion (U2.H6 U21.6), TIDA-01452_SmartSensorIF (J17.8)
CC2650_GPS_I2C_SDA: TIDA-01452_I3Mote (R110.2), TIDA-01452_Sensors (R118.1), TIDA-01452_WirelessConnectivity (U9.36), TIDA-01452_DataFusion (U2.J5 U21.5), TIDA-01452_SmartSensorIF (J17.10)
CC2650_GPS_LIS_IRQ: TIDA-01452_Sensors (U27.12), TIDA-01452_WirelessConnectivity (U9.43), TIDA-01452_DataFusion (U2.F8)
CC2650_GPS_TMP_IRQ: TIDA-01452_Sensors (R36.2 U6.C2), TIDA-01452_WirelessConnectivity (U9.42), TIDA-01452_DataFusion (U2.F7)
CC2650_JTAG_TCK: TIDA-01452_I3Mote (J2.4 JP1.2 R100.2), TIDA-01452_WirelessConnectivity (U9.25)
CC2650_JTAG_TDI: TIDA-01452_I3Mote (J2.8), TIDA-01452_WirelessConnectivity (U9.27)
CC2650_JTAG_TDO: TIDA-01452_WirelessConnectivity (U9.26), TIDA-01452_DataFusion (U2.B3)
CC2650_JTAG_TMS: TIDA-01452_I3Mote (J2.2), TIDA-01452_WirelessConnectivity (U9.24), TIDA-01452_DataFusion (U2.B2)
CC2650_nRESET: TIDA-01452_I3Mote (J2.10 R30.1), TIDA-01452_DEBUG_USB (J18.8), TIDA-01452_WirelessConnectivity (C68.1 R44.2 U9.35), TIDA-01452_DataFusion (C45.1 R24.2 U2.B6)
CC2650_SSM_IRQ: TIDA-01452_I3Mote (J19.10), TIDA-01452_WirelessConnectivity (U9.32), TIDA-01452_DataFusion (U2.H9)
CC2650_SSM_SPI_CLK: TIDA-01452_I3Mote (J19.2), TIDA-01452_WirelessConnectivity (U9.30), TIDA-01452_DataFusion (U2.F1)
CC2650_SSM_SPI_CS: TIDA-01452_I3Mote (J19.4), TIDA-01452_WirelessConnectivity (U9.31), TIDA-01452_DataFusion (U2.E4)
CC2650_SSM_SPI_MISO: TIDA-01452_I3Mote (J19.6), TIDA-01452_WirelessConnectivity (U9.28), TIDA-01452_DataFusion (U2.E3)
CC2650_SSM_SPI_MOSI: TIDA-01452_I3Mote (J19.8), TIDA-01452_WirelessConnectivity (U9.29), TIDA-01452_DataFusion (U2.F4)
EH_nEN: TIDA-01452_PowerManagement (Q7.A2 Q7.C1 R139.2 TP2.1), TIDA-01452_DEBUG_USB (J18.4)
EH_VOUT_REG: TIDA-01452_PowerManagement (Q7.C2 R68.1), TIDA-01452_PWR_EH (C86.2 TP30.1 U26.1)
FTDI_UART1.RX: TIDA-01452_DEBUG_USB (J18.5), TIDA-01452_DataFusion (U2.D4)
FTDI_UART1.TX: TIDA-01452_DEBUG_USB (J18.3), TIDA-01452_DataFusion (U2.C4)
IRQ_MSP432_SSM: TIDA-01452_I3Mote (J19.9), TIDA-01452_DataFusion (U2.H8), TIDA-01452_SmartSensorIF (J17.16)
JTAG_TDO: TIDA-01452_I3Mote (J2.6), TIDA-01452_DataFusion (U2.A3)
MSP432_BSL: TIDA-01452_DEBUG_USB (J18.6), TIDA-01452_DataFusion (U2.A1)
MSP432_JTAG_TCK: TIDA-01452_I3Mote (JP1.1 R100.1), TIDA-01452_DataFusion (U2.A2)
MSP432_SSM_PWM1: TIDA-01452_DataFusion (U2.B8), TIDA-01452_SmartSensorIF (J17.15)
MSP432_SSM_PWM2: TIDA-01452_DataFusion (U2.B7), TIDA-01452_SmartSensorIF (J17.17)
MSP432_SSM_SPI_CLK: TIDA-01452_I3Mote (J19.1), TIDA-01452_DataFusion (U2.C1), TIDA-01452_SmartSensorIF (J17.12)
MSP432_SSM_SPI_CS: TIDA-01452_I3Mote (J19.3), TIDA-01452_DataFusion (U2.D3), TIDA-01452_SmartSensorIF (J17.14)
MSP432_SSM_SPI_MISO: TIDA-01452_I3Mote (J19.5), TIDA-01452_DataFusion (U2.E1), TIDA-01452_SmartSensorIF (J17.11)
MSP432_SSM_SPI_MOSI: TIDA-01452_I3Mote (J19.7), TIDA-01452_DataFusion (U2.D1), TIDA-01452_SmartSensorIF (J17.13)
PWR_MGMT.SSM_5V_EN: TIDA-01452_PowerManagement (R55.1 U12.6), TIDA-01452_WirelessConnectivity (U9.41), TIDA-01452_DataFusion (U2.G3)
PWR_MGMT.SSM_PWR_nEN: TIDA-01452_PowerManagement (R91.1 R93.2 U22.6), TIDA-01452_WirelessConnectivity (U9.38), TIDA-01452_DataFusion (U2.G1)

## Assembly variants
001: all parts fitted
002: all parts fitted
003: not fitted C1 C2 C3 C4 C5 C6 C8 C9 C10 C11 C12 C13 C14 C15 C16 C17 C19 C20 C21 C22 C23 C24 C25 C26 C27 C28 C29 C30 C31 C32 C33 C34 C35 D3 J5 JP6 JP24 JP25 L1 Q1 Q4 R1 R5 R7 R8 R9 R10 R11 R12 R13 R14 R15 R16 R17 R18 R19 R20 R21 R22 R23 R26 R27 R28 R29 R84 R85 R86 R87 R131 R132 U1 Y1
